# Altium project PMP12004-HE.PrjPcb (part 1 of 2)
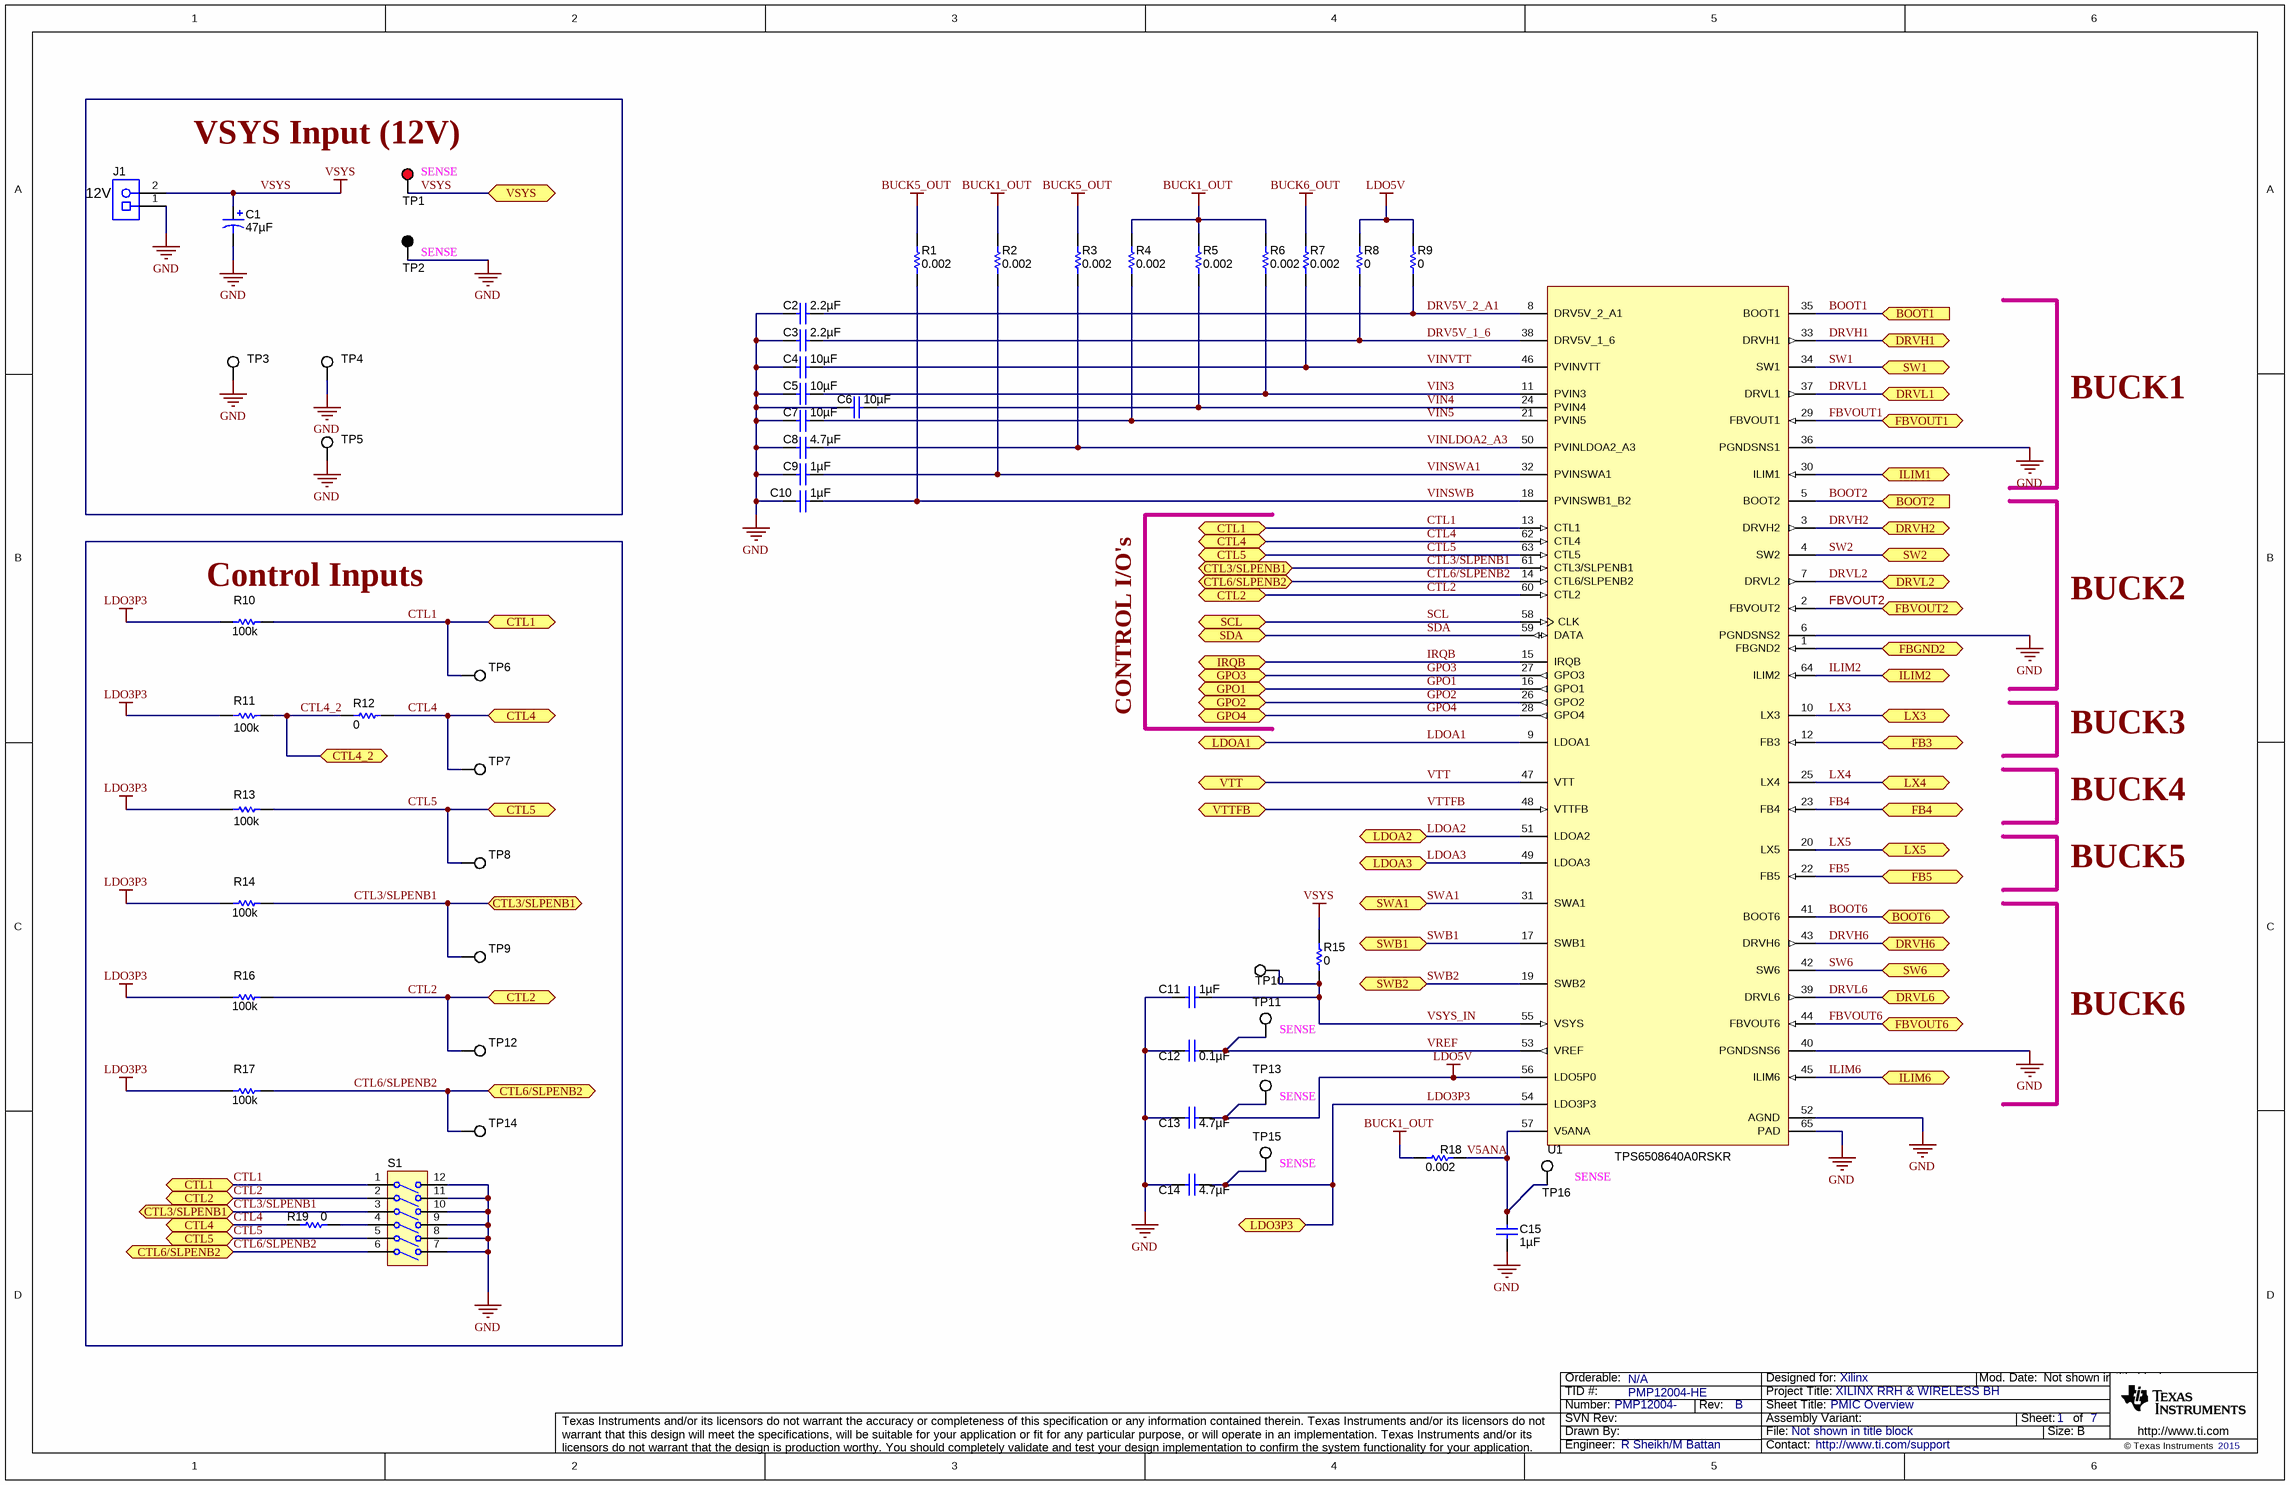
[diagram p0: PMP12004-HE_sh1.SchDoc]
TID: PMP12004-HE; TechSupport: http://www.ti.com/support; SCH_Rev: B; PRJ_Title: XILINX RRH & WIRELESS BH; PRJ_Number: PMP12004-; PRJ_Engineer: R Sheikh/M Battan; PRJ_Customer: Xilinx; PCB_Rev: RevA; PCB_Layout: Tessolve; EVM_Orderable: N/A; CopyrightYear: 2015
7 sheets, 361 parts. Net scope: flat (ports and power ports of the same name join across sheets).
Board file: PMP12004RevA.PcbDoc
Sheets:
  PMP12004-HE_sh1.SchDoc
  PMP12004-HE_sh2.SchDoc
  PMP12004-HE_sh3.SchDoc
  PMP12004-HE_sh4.SchDoc
  PMP12004-HE_sh5.SchDoc
  PMP12004-HE_sh6.SchDoc
  PMP12004-HE_Hardware.SchDoc

## Sheet PMP12004-HE_sh1.SchDoc: PMIC Overview
size 431 x 279 mm; Date: Not shown in title block; ApprovedBy: Not shown in title block; CheckedBy: Not shown in title block; Author: Not shown in title block; CompanyName: Not shown in title block; Engineer: Not shown in title block; Organization: Not shown in title block; Address1: Not shown in title block; Address2: Not shown in title block; Address3: Not shown in title block; Address4: Not shown in title block; DocumentNumber: 1; Revision: Use project parameter SCH_Rev; SheetNumber: 1; SheetTotal: 7; PageSetup: Record=PageOptions¦CenterHorizontal=True¦CenterVertical=True¦PrintScale=1.00¦XCorrection=1.00¦YCorrection=1.00¦PrintKind=0¦BorderSize=5000000¦LeftOffset=0¦BottomOffset=0¦Orientation=2¦PaperLength=1000¦PaperWidth=1000¦Scale=100¦PaperSource=15¦PrintQuality=600¦MediaType=1¦DitherType=10¦PaperKind=Letter¦PrintScaleMode=1

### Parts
C1  ValueDisplayed: 47µF  [7343-43]  (hidden comment: T495X476K035ATE300)
C2  ValueDisplayed: 2.2µF  [0402]  (hidden comment: CL05A225KQ5NNNC)
C3  ValueDisplayed: 2.2µF  [0402]  (hidden comment: CL05A225KQ5NNNC)
C4  ValueDisplayed: 10µF  [0402]  (hidden comment: CL05A106MP5NUNC)
C5  ValueDisplayed: 10µF  [0402]  (hidden comment: CL05A106MP5NUNC)
C6  ValueDisplayed: 10µF  [0402]  (hidden comment: CL05A106MP5NUNC)
C7  ValueDisplayed: 10µF  [0402]  (hidden comment: CL05A106MP5NUNC)
C8  ValueDisplayed: 4.7µF  [0402]  (hidden comment: GRM155R60J475ME47D)
C9  ValueDisplayed: 1µF  [0402]  (hidden comment: GRM155R61A105KE15D)
C10  ValueDisplayed: 1µF  [0402]  (hidden comment: GRM155R61A105KE15D)
C11  ValueDisplayed: 1µF  [0402]  (hidden comment: GRM155R6YA105KE11D)
C12  ValueDisplayed: 0.1µF  [0402]  (hidden comment: GRM155R61A104KA01D)
C13  ValueDisplayed: 4.7µF  [0603]  (hidden comment: GRM188R61A475ME15)
C14  ValueDisplayed: 4.7µF  [0603]  (hidden comment: GRM188R61A475ME15)
C15  ValueDisplayed: 1µF  [0402]  (hidden comment: GRM155R61A105KE15D)
J1  1935776  [Phoenix_1935776]  (value not drawn)
R1  ValueDisplayed: 0.002  [0508]  (hidden comment: KRL2012E-M-R002-G-T5)
R2  ValueDisplayed: 0.002  [0508]  (hidden comment: KRL2012E-M-R002-G-T5)
R3  ValueDisplayed: 0.002  [0508]  (hidden comment: KRL2012E-M-R002-G-T5)
R4  ValueDisplayed: 0.002  [0508]  (hidden comment: KRL2012E-M-R002-G-T5)
R5  ValueDisplayed: 0.002  [0508]  (hidden comment: KRL2012E-M-R002-G-T5)
R6  ValueDisplayed: 0.002  [0508]  (hidden comment: KRL2012E-M-R002-G-T5)
R7  ValueDisplayed: 0.002  [0508]  (hidden comment: KRL2012E-M-R002-G-T5)
R8  ValueDisplayed: 0  [0402]  (hidden comment: CRCW04020000Z0ED)
R9  ValueDisplayed: 0  [0402]  (hidden comment: CRCW04020000Z0ED)
R10  ValueDisplayed: 100k  [0402]  (hidden comment: CRCW0402100KJNED)
R11  value 100k  [0402]  (hidden comment: CRCW0402100KJNED)
R12  ValueDisplayed: 0  [0402]  (hidden comment: CRCW04020000Z0ED)
R13  Value_Code: 100k  [0402]  (hidden comment: CRCW0402100KJNED)
R14  ValueDisplayed: 100k  [0402]  (hidden comment: CRCW0402100KJNED)
R15  ValueDisplayed: 0  [0402]  (hidden comment: CRCW04020000Z0ED)
R16  ValueDisplayed: 100k  [0402]  (hidden comment: CRCW0402100KJNED)
R17  ValueDisplayed: 100k  [0402]  (hidden comment: CRCW0402100KJNED)
R18  ValueDisplayed: 0.002  [0508]  (hidden comment: KRL2012E-M-R002-G-T5)
R19  value 0  [0402]  (hidden comment: CRCW04020000Z0ED)
S1  SDA06H1SBD  [SW_SDA06H1SBD]  (value not drawn)
TP1  5000  [Keystone5000]  (value not drawn)
TP2  5001  [Keystone5001]  (value not drawn)
TP3  5015  [Testpoint_Keystone_Miniature]  (value not drawn)
TP4  5015  [Testpoint_Keystone_Miniature]  (value not drawn)
TP5  5015  [Testpoint_Keystone_Miniature]  (value not drawn)
TP6  5015  [Testpoint_Keystone_Miniature]  (value not drawn)
TP7  5015  [Testpoint_Keystone_Miniature]  (value not drawn)
TP8  5015  [Testpoint_Keystone_Miniature]  (value not drawn)
TP9  5015  [Testpoint_Keystone_Miniature]  (value not drawn)
TP10  5015  [Testpoint_Keystone_Miniature]  (value not drawn)
TP11  5015  [Testpoint_Keystone_Miniature]  (value not drawn)
TP12  5015  [Testpoint_Keystone_Miniature]  (value not drawn)
TP13  5015  [Testpoint_Keystone_Miniature]  (value not drawn)
TP14  5015  [Testpoint_Keystone_Miniature]  (value not drawn)
TP15  5015  [Testpoint_Keystone_Miniature]  (value not drawn)
TP16  5015  [Testpoint_Keystone_Miniature]  (value not drawn)
U1  TPS6508640A0RSKR  [RSK0064C]

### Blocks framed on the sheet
VSYS Input (12V): C1 J1 TP1-TP5
Control Inputs: R10-R14 R16 R17 R19 S1 TP6-TP9 TP12 TP14

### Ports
BOOT1 (in), BOOT2 (in), BOOT6 (bidir), CTL1 (bidir), CTL2 (bidir), CTL3/SLPENB1 (bidir), CTL4 (bidir), CTL4_2 (bidir), CTL5 (bidir), CTL6/SLPENB2 (bidir), DRVH1 (bidir), DRVH2 (bidir), DRVH6 (bidir), DRVL1 (bidir), DRVL2 (bidir), DRVL6 (bidir), FB3 (bidir), FB4 (bidir), FB5 (bidir), FBGND2 (bidir), FBVOUT1 (bidir), FBVOUT2 (bidir), FBVOUT6 (bidir), GPO1 (bidir), GPO2 (bidir), GPO3 (bidir), GPO4 (bidir), ILIM1 (bidir), ILIM2 (bidir), ILIM6 (bidir), IRQB (bidir), LDO3P3 (bidir), LDOA1 (bidir), LDOA2 (bidir), LDOA3 (bidir), LX3 (bidir), LX4 (bidir), LX5 (bidir), SCL (bidir), SDA (bidir), SW1 (bidir), SW2 (bidir), SW6 (bidir), SWA1 (bidir), SWB1 (bidir), SWB2 (bidir), VSYS (bidir), VTT (bidir), VTTFB (bidir)

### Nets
BUCK1_OUT: R2.1 R4.1 R5.1 R6.1 R18.2
BUCK5_OUT: R1.1 R3.1
BUCK6_OUT: R7.1
GND: C1.2(-) C2.2 C3.2 C4.2 C5.2 C6.2 C7.2 C8.2 C9.2 C10.2 C11.2 C12.2 C13.2 C14.2 C15.2 J1.1 S1.7(6A) S1.8(5A) S1.9(4A) S1.10(3A) S1.11(2A) S1.12(1A) TP2.1 TP3.1 TP4.1 TP5.1 U1.6(PGNDSNS2) U1.36(PGNDSNS1) U1.40(PGNDSNS6) U1.52(AGND) U1.65(PAD)
LDO3P3: C14.1 R10.2 R11.2 R13.2 R14.2 R16.2 R17.2 TP15.1 U1.54(LDO3P3) ; port LDO3P3
LDO5V: C13.1 R8.1 R9.1 TP13.1 U1.56(LDO5P0)
VSYS: C1.1(+) J1.2 R15.2 TP1.1 ; port VSYS
BOOT1: U1.35(BOOT1) ; port BOOT1
BOOT2: U1.5(BOOT2) ; port BOOT2
BOOT6: U1.41(BOOT6) ; port BOOT6
CTL1: R10.1 S1.1 TP6.1 U1.13(CTL1) ; port CTL1
CTL2: R16.1 S1.2 TP12.1 U1.60(CTL2) ; port CTL2
CTL3/SLPENB1: R14.1 S1.3 TP9.1 U1.61(CTL3/SLPENB1) ; port CTL3/SLPENB1
CTL4: R12.2 R19.1 TP7.1 U1.62(CTL4) ; port CTL4
CTL4_2: R11.1 R12.1 ; port CTL4_2
CTL5: R13.1 S1.5 TP8.1 U1.63(CTL5) ; port CTL5
CTL6/SLPENB2: R17.1 S1.6 TP14.1 U1.14(CTL6/SLPENB2) ; port CTL6/SLPENB2
DRV5V_1_6: C3.1 R8.2 U1.38(DRV5V_1_6)
DRV5V_2_A1: C2.1 R9.2 U1.8(DRV5V_2_A1)
DRVH1: U1.33(DRVH1) ; port DRVH1
DRVH2: U1.3(DRVH2) ; port DRVH2
DRVH6: U1.43(DRVH6) ; port DRVH6
DRVL1: U1.37(DRVL1) ; port DRVL1
DRVL2: U1.7(DRVL2) ; port DRVL2
DRVL6: U1.39(DRVL6) ; port DRVL6
FB3: U1.12(FB3) ; port FB3
FB4: U1.23(FB4) ; port FB4
FB5: U1.22(FB5) ; port FB5
FBGND2: U1.1(FBGND2) ; port FBGND2
FBVOUT1: U1.29(FBVOUT1) ; port FBVOUT1
FBVOUT2: U1.2(FBVOUT2) ; port FBVOUT2
FBVOUT6: U1.44(FBVOUT6) ; port FBVOUT6
GPO1: U1.16(GPO1) ; port GPO1
GPO2: U1.26(GPO2) ; port GPO2
GPO3: U1.27(GPO3) ; port GPO3
GPO4: U1.28(GPO4) ; port GPO4
ILIM1: U1.30(ILIM1) ; port ILIM1
ILIM2: U1.64(ILIM2) ; port ILIM2
ILIM6: U1.45(ILIM6) ; port ILIM6
IRQB: U1.15(IRQB) ; port IRQB
LDOA1: U1.9(LDOA1) ; port LDOA1
LDOA2: U1.51(LDOA2) ; port LDOA2
LDOA3: U1.49(LDOA3) ; port LDOA3
LX3: U1.10(LX3) ; port LX3
LX4: U1.25(LX4) ; port LX4
LX5: U1.20(LX5) ; port LX5
SCL: U1.58(CLK) ; port SCL
SDA: U1.59(DATA) ; port SDA
SW1: U1.34(SW1) ; port SW1
SW2: U1.4(SW2) ; port SW2
SW6: U1.42(SW6) ; port SW6
SWA1: U1.31(SWA1) ; port SWA1
SWB1: U1.17(SWB1) ; port SWB1
SWB2: U1.19(SWB2) ; port SWB2
V5ANA: C15.1 R18.1 TP16.1 U1.57(V5ANA)
VIN3: C5.1 R6.2 U1.11(PVIN3)
VIN4: C6.1 R5.2 U1.24(PVIN4)
VIN5: C7.1 R4.2 U1.21(PVIN5)
VINLDOA2_A3: C8.1 R3.2 U1.50(PVINLDOA2_A3)
VINSWA1: C9.1 R2.2 U1.32(PVINSWA1)
VINSWB: C10.1 R1.2 U1.18(PVINSWB1_B2)
VINVTT: C4.1 R7.2 U1.46(PVINVTT)
VREF: C12.1 TP11.1 U1.53(VREF)
VSYS_IN: C11.1 R15.1 TP10.1 U1.55(VSYS)
VTT: U1.47(VTT) ; port VTT
VTTFB: U1.48(VTTFB) ; port VTTFB
NetR19_2: R19.2 S1.4

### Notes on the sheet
- (near J1) 12V
- (near TP1) SENSE
- (near TP2) SENSE
- BUCK1
- BUCK2
- CONTROL I/O's
- BUCK3
- BUCK4
- BUCK5
- (near TP11) SENSE
- BUCK6
- (near TP13) SENSE
- (near TP15) SENSE
- SENSE

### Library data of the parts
C1 = T495X476K035ATE300: CAP, TA, 47 µF, 35 V, +/- 10%, 0.3 ohm, SMD; Manufacturer: Kemet; Polarized: Y; CompType: Capacitor; Value: 47uF; U/M: EA; Cap_F: 0.000047; Tolerance_%: 10; Value1: 0.3 ohm; VDC_V: 35; Value2: 35V; ESR_ohm: 0.3; IRMS_A: 0.667; TaMin_C: -55; TaMax_C: 125; Cap_Case: X
C2 C3 = CL05A225KQ5NNNC: CAP, CERM, 2.2 µF, 6.3 V, +/- 10%, X5R, 0402; Manufacturer: Samsung; Polarized: N; CompType: Capacitor; Value: 2.2uF; U/M: EA; Cap_F: 0.0000022; Tolerance_%: 10; Value1: Unknown; VDC_V: 6.3; Value2: 6.3V; TaMin_C: -55; TaMax_C: 85
C4-C7 = CL05A106MP5NUNC: CAP, CERM, 10 µF, 10 V, +/- 20%, X5R, 0402; Manufacturer: Samsung Electro-Mechanics; Polarized: N; CompType: Capacitor; Value: 10uF; U/M: EA; Cap_F: 0.00001; Tolerance_%: 20; Value1: Unknown; VDC_V: 10; Value2: 10V; TaMin_C: -55; TaMax_C: 85
C8 = GRM155R60J475ME47D: CAP, CERM, 4.7 µF, 6.3 V, +/- 20%, X5R, 0402; Manufacturer: MuRata; Polarized: N; CompType: Capacitor; Value: 4.7uF; U/M: EA; Cap_F: 0.0000047; Tolerance_%: 20; Value1: Unknown; VDC_V: 6.3; Value2: 6.3V; TaMin_C: -55; TaMax_C: 85
C9 C10 C15 = GRM155R61A105KE15D: CAP, CERM, 1 µF, 10 V, +/- 10%, X5R, 0402; Manufacturer: MuRata; Polarized: N; CompType: Capacitor; Value: 1uF; U/M: EA; Cap_F: 0.000001; Tolerance_%: 10; Value1: Unknown; Value2: 10V; TaMin_C: -55; TaMax_C: 85
C11 = GRM155R6YA105KE11D: CAP, CERM, 1 µF, 35 V, +/- 10%, X5R, 0402; Manufacturer: MuRata; Polarized: N; CompType: Capacitor; Value: 1uF; U/M: EA; Cap_F: 0.000001; Tolerance_%: 10; Value1: Unknown; VDC_V: 35; Value2: 35V; TaMin_C: -55; TaMax_C: 85
C12 = GRM155R61A104KA01D: CAP, CERM, 0.1 µF, 10 V, +/- 10%, X5R, 0402; Manufacturer: MuRata; Polarized: N; CompType: Capacitor; Value: 0.1uF; U/M: EA; Cap_F: 0.0000001; Tolerance_%: 10; Value1: Unknown; Value2: 10V; TaMin_C: -55; TaMax_C: 85
C13 C14 = GRM188R61A475ME15: CAP, CERM, 4.7 µF, 10 V, +/- 20%, X5R, 0603; Manufacturer: MuRata; Polarized: N; CompType: Capacitor; Value: 4.7uF; U/M: EA; Cap_F: 0.0000047; Tolerance_%: 20; Value1: Unknown; VDC_V: 10; Value2: 10V; TaMin_C: -55; TaMax_C: 85; AEC Category: Q200
J1 = 1935776: Terminal Block, 2x1, 5mm, Green, TH; Manufacturer: Phoenix Contact; SymbolCreator: a0412235; U/M: EA
R1-R7 R18 = KRL2012E-M-R002-G-T5: RES, 0.002, 2%, 1 W, 0508; Manufacturer: Susumu Co Ltd; CompType: Resistor; Value: 0.002; Value_Code: 2L000; Tolerance_%: 2; Power_W: 1; Value2: 1W; TempCo: 100 ppm/C; U/M: EA
R8 R9 R12 R15 = CRCW04020000Z0ED: RES, 0, 5%, 0.063 W, 0402; Manufacturer: Vishay-Dale; CompType: Resistor; Value: 0; Value_Code: 0000; Tolerance_%: 5; Power_W: 0.063; Value2: 0.063W; VDC_V: 50; TempCo: 200 ppm/C; EIA_Code: E24; U/M: EA
R10 R13 R14 R16 R17 = CRCW0402100KJNED: RES, 100 k, 5%, 0.063 W, 0402; Manufacturer: Vishay-Dale; CompType: Resistor; Value: 100k; Res_ohm: 100000; Tolerance_%: 5; Power_W: 0.063; Value2: 0.063W; VDC_V: 50; TempCo: 200 ppm/C; EIA_Code: E24; U/M: EA
R11 = CRCW0402100KJNED: RES, 100 k, 5%, 0.063 W, 0402; Manufacturer: Vishay-Dale; CompType: Resistor; ValueDisplayed: DNP; Res_ohm: 100000; Tolerance_%: 5; Power_W: 0.063; Value2: 0.063W; VDC_V: 50; TempCo: 200 ppm/C; EIA_Code: E24; U/M: EA
R19 = CRCW04020000Z0ED: RES, 0, 5%, 0.063 W, 0402; Manufacturer: Vishay-Dale; CompType: Resistor; ValueDisplayed: DNP; Value_Code: 0000; Tolerance_%: 5; Power_W: 0.063; Value2: 0.063W; TempCo: 200 ppm/C; EIA_Code: E24; U/M: EA
S1 = SDA06H1SBD: Switch, SPST 6Pos, SMT; Manufacturer: C&K Components; SymbolCreator: a0799628; VDC_V: 24; SwitchFunction: Off-On; PositionCount: 6; CurrentRating_mA: 25
TP1 = 5000: Test Point, Miniature, Red, TH; Manufacturer: Keystone; CompType: Test Point Loop; U/M: EA
TP2 = 5001: Test Point, Miniature, Black, TH; Manufacturer: Keystone; CompType: Test Point Loop; U/M: EA
TP3-TP16 = 5015: Test Point, Miniature, SMT; Manufacturer: Keystone; CompType: Test Point Loop; U/M: EA
U1 = TPS650860A0RSKR: Wide VIN, Flexible, Simple, Small, and Low-Cost PMU; Alternate PartNumber: TPS6508640A0RSKT; Manufacturer: Texas Instruments; SymbolCreator: Altium; CompType: IC; U/M: EA

## Sheet PMP12004-HE_sh2.SchDoc: 3.3V & VCCPINT Rails
size 431 x 279 mm; Date: Not shown in title block; ApprovedBy: Not shown in title block; CheckedBy: Not shown in title block; Author: Not shown in title block; CompanyName: Not shown in title block; Engineer: Not shown in title block; Organization: Not shown in title block; Address1: Not shown in title block; Address2: Not shown in title block; Address3: Not shown in title block; Address4: Not shown in title block; DocumentNumber: 2; Revision: Use project parameter SCH_Rev; SheetNumber: 2; SheetTotal: 7; PageSetup: Record=PageOptions¦CenterHorizontal=True¦CenterVertical=True¦PrintScale=1.00¦XCorrection=1.00¦YCorrection=1.00¦PrintKind=0¦BorderSize=5000000¦LeftOffset=0¦BottomOffset=0¦Orientation=2¦PaperLength=1000¦PaperWidth=1000¦Scale=100¦PaperSource=15¦PrintQuality=600¦MediaType=1¦DitherType=10¦PaperKind=Letter¦PrintScaleMode=1
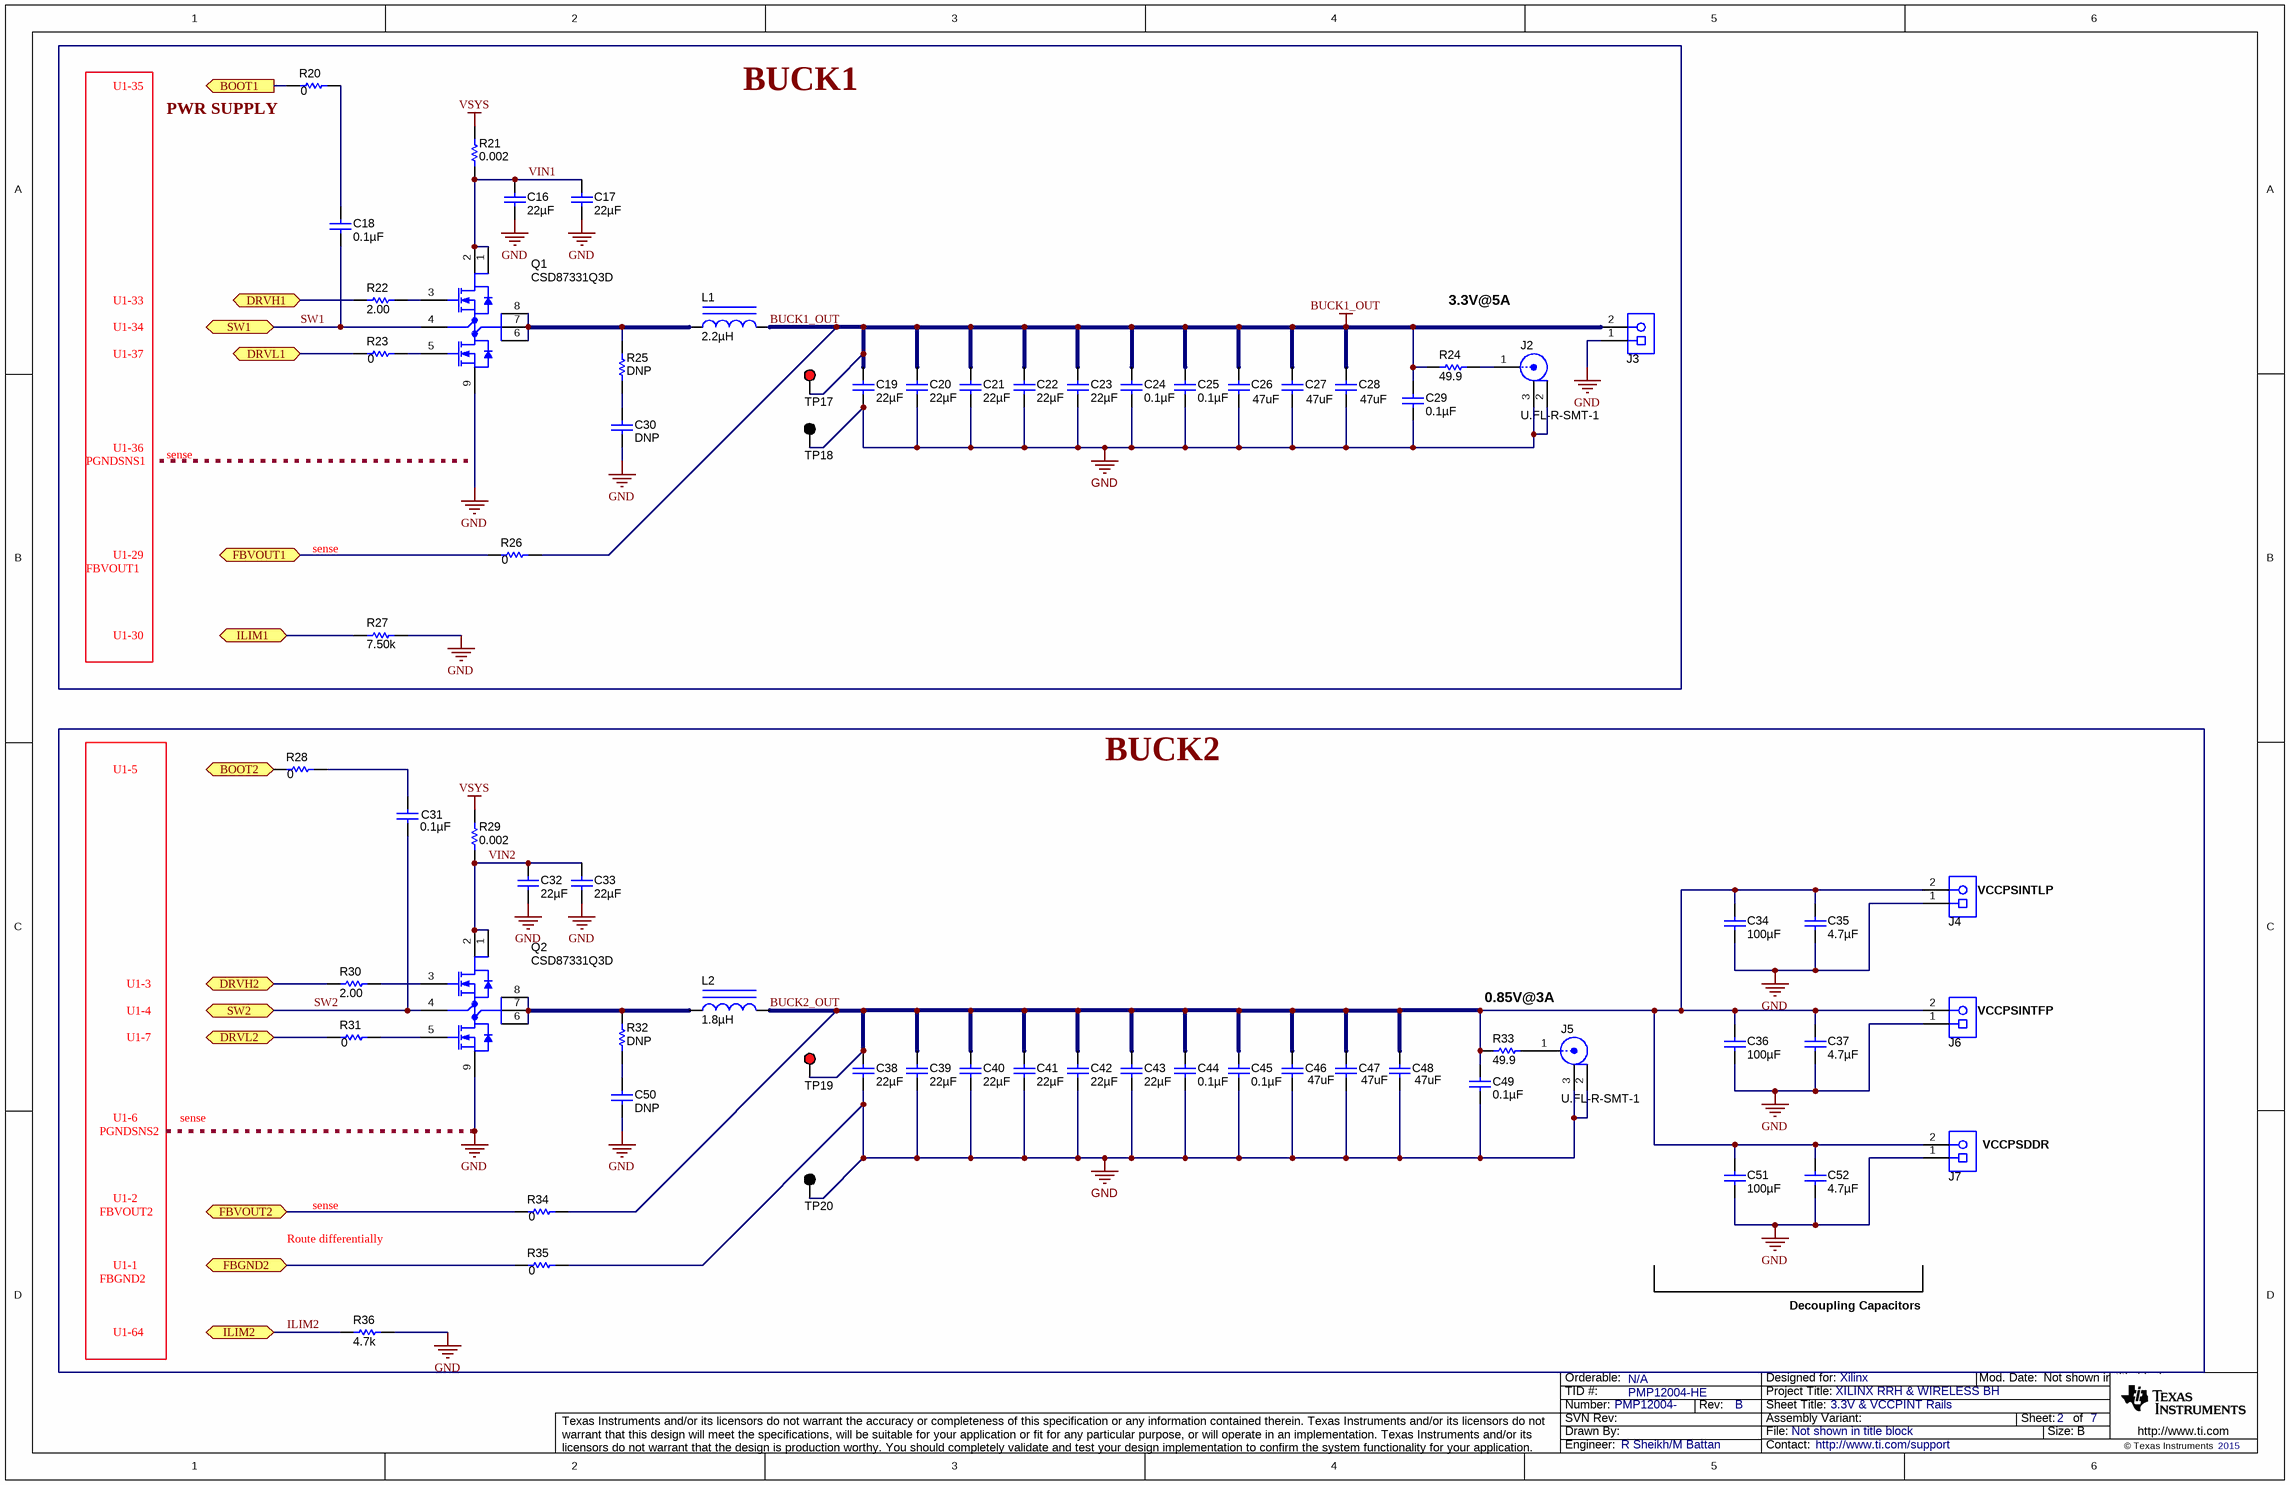
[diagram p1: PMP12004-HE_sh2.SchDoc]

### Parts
C16  ValueDisplayed: 22µF  [0805_HV]  (hidden comment: GRM21BR61E226ME44)
C17  ValueDisplayed: 22µF  [0805_HV]  (hidden comment: GRM21BR61E226ME44)
C18  ValueDisplayed: 0.1µF  [0402]  (hidden comment: GRM155R61A104KA01D)
C19  ValueDisplayed: 22µF  [0603]  (hidden comment: GRM188R60J226MEA0J)
C20  ValueDisplayed: 22µF  [0603]  (hidden comment: GRM188R60J226MEA0J)
C21  ValueDisplayed: 22µF  [0603]  (hidden comment: GRM188R60J226MEA0J)
C22  ValueDisplayed: 22µF  [0603]  (hidden comment: GRM188R60J226MEA0J)
C23  ValueDisplayed: 22µF  [0603]  (hidden comment: GRM188R60J226MEA0J)
C24  ValueDisplayed: 0.1µF  [0402]  (hidden comment: GRM155R61A104KA01D)
C25  ValueDisplayed: 0.1µF  [0402]  (hidden comment: GRM155R61A104KA01D)
C26  value 47uF  [0805_HV]  (hidden comment: GRM21BR61A476ME15)
C27  value 47uF  [0805_HV]  (hidden comment: GRM21BR61A476ME15)
C28  value 47uF  [0805_HV]  (hidden comment: GRM21BR61A476ME15)
C29  ValueDisplayed: 0.1µF  [0402]  (hidden comment: GRM155R61E104KA87D)
C30  ValueDisplayed: DNP  [0402]  (hidden comment: GRM155R71E682KA01D)
C31  ValueDisplayed: 0.1µF  [0402]  (hidden comment: GRM155R61A104KA01D)
C32  ValueDisplayed: 22µF  [0805_HV]  (hidden comment: GRM21BR61E226ME44)
C33  ValueDisplayed: 22µF  [0805_HV]  (hidden comment: GRM21BR61E226ME44)
C34  ValueDisplayed: 100µF  [0805_HV]  (hidden comment: GRM21BR60G107ME15L)
C35  ValueDisplayed: 4.7µF  [0603]  (hidden comment: GRM188R60J475ME19D)
C36  ValueDisplayed: 100µF  [0805_HV]  (hidden comment: GRM21BR60G107ME15L)
C37  ValueDisplayed: 4.7µF  [0603]  (hidden comment: GRM188R60J475ME19D)
C38  ValueDisplayed: 22µF  [0603]  (hidden comment: GRM188R60J226MEA0J)
C39  ValueDisplayed: 22µF  [0603]  (hidden comment: GRM188R60J226MEA0J)
C40  ValueDisplayed: 22µF  [0603]  (hidden comment: GRM188R60J226MEA0J)
C41  ValueDisplayed: 22µF  [0603]  (hidden comment: GRM188R60J226MEA0J)
C42  ValueDisplayed: 22µF  [0603]  (hidden comment: GRM188R60J226MEA0J)
C43  ValueDisplayed: 22µF  [0603]  (hidden comment: GRM188R60J226MEA0J)
C44  ValueDisplayed: 0.1µF  [0402]  (hidden comment: GRM155R61A104KA01D)
C45  ValueDisplayed: 0.1µF  [0402]  (hidden comment: GRM155R61A104KA01D)
C46  value 47uF  [0805_HV]  (hidden comment: GRM21BR61A476ME15)
C47  value 47uF  [0805_HV]  (hidden comment: GRM21BR61A476ME15)
C48  value 47uF  [0805_HV]  (hidden comment: GRM21BR61A476ME15)
C49  ValueDisplayed: 0.1µF  [0402]  (hidden comment: GRM155R61E104KA87D)
C50  ValueDisplayed: DNP  [0402]  (hidden comment: GRM155R71E682KA01D)
C51  ValueDisplayed: 100µF  [0805_HV]  (hidden comment: GRM21BR60G107ME15L)
C52  ValueDisplayed: 4.7µF  [0603]  (hidden comment: GRM188R60J475ME19D)
J2  U.FL-R-SMT-1  [CONN_UFL-R-SMT-1]
J3  1935776  [Phoenix_1935776]  (value not drawn)
J4  1935776  [Phoenix_1935776]  (value not drawn)
J5  U.FL-R-SMT-1  [CONN_UFL-R-SMT-1]
J6  1935776  [Phoenix_1935776]  (value not drawn)
J7  1935776  [Phoenix_1935776]  (value not drawn)
L1  ValueDisplayed: 2.2µH  [WE-LHMI_1040]  (hidden comment: 74437368022)
L2  ValueDisplayed: 1.8µH  [WE-HC6]  (hidden comment: 744325180)
Q1  CSD87331Q3D  [TRANS_NexFET_Q3D]
Q2  CSD87331Q3D  [TRANS_NexFET_Q3D]
R20  ValueDisplayed: 0  [0402]  (hidden comment: CRCW04020000Z0ED)
R21  ValueDisplayed: 0.002  [0508]  (hidden comment: KRL2012E-M-R002-G-T5)
R22  ValueDisplayed: 2.00  [0402]  (hidden comment: CRCW04022R00FKED)
R23  ValueDisplayed: 0  [0402]  (hidden comment: CRCW04020000Z0ED)
R24  ValueDisplayed: 49.9  [0402]  (hidden comment: CRCW040249R9FKED)
R25  ValueDisplayed: DNP  [0402]  (hidden comment: CRCW04022R20JNED)
R26  ValueDisplayed: 0  [0402]  (hidden comment: CRCW04020000Z0ED)
R27  ValueDisplayed: 7.50k  [0402]  (hidden comment: CRCW04027K50FKED)
R28  ValueDisplayed: 0  [0402]  (hidden comment: CRCW04020000Z0ED)
R29  ValueDisplayed: 0.002  [0508]  (hidden comment: KRL2012E-M-R002-G-T5)
R30  ValueDisplayed: 2.00  [0402]  (hidden comment: CRCW04022R00FKED)
R31  ValueDisplayed: 0  [0402]  (hidden comment: CRCW04020000Z0ED)
R32  ValueDisplayed: DNP  [0402]  (hidden comment: CRCW04022R20JNED)
R33  ValueDisplayed: 49.9  [0402]  (hidden comment: CRCW040249R9FKED)
R34  ValueDisplayed: 0  [0402]  (hidden comment: CRCW04020000Z0ED)
R35  ValueDisplayed: 0  [0402]  (hidden comment: CRCW04020000Z0ED)
R36  ValueDisplayed: 4.7k  [0402]  (hidden comment: CRCW04024K70JNED)
TP17  5000  [Keystone5000]  (value not drawn)
TP18  5001  [Keystone5001]  (value not drawn)
TP19  5000  [Keystone5000]  (value not drawn)
TP20  5001  [Keystone5001]  (value not drawn)

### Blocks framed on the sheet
BUCK1: C16-C30 J2 J3 L1 Q1 R20-R27 TP17 TP18
BUCK2: C31-C52 J4-J7 L2 Q2 R28-R36 TP19 TP20

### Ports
BOOT1 (out), BOOT2 (out), DRVH1 (bidir), DRVH2 (bidir), DRVL1 (bidir), DRVL2 (bidir), FBGND2 (bidir), FBVOUT1 (bidir), FBVOUT2 (bidir), ILIM1 (bidir), ILIM2 (bidir), SW1 (bidir), SW2 (bidir)

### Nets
BUCK1_OUT: C19.1 C20.1 C21.1 C22.1 C23.1 C24.1 C25.1 C26.1 C27.1 C28.1 C29.1 J3.2 L1.2 R24.1 R26.2 TP17.1
GND: C16.2 C17.2 C19.2 C20.2 C21.2 C22.2 C23.2 C24.2 C25.2 C26.2 C27.2 C28.2 C29.2 C30.2 C32.2 C33.2 C34.2 C35.2 C36.2 C37.2 C38.2 C39.2 C40.2 C41.2 C42.2 C43.2 C44.2 C45.2 C46.2 C47.2 C48.2 C49.2 C50.2 C51.2 C52.2 J2.2 J2.3 J3.1 J4.1 J5.2 J5.3 J6.1 J7.1 Q1.9(PGND) Q2.9(PGND) R27.2 R35.2 R36.2 TP18.1 TP20.1
VSYS: R21.1 R29.1
BOOT1: R20.1 ; port BOOT1
BOOT2: R28.1 ; port BOOT2
BUCK2_OUT: C34.1 C35.1 C36.1 C37.1 C38.1 C39.1 C40.1 C41.1 C42.1 C43.1 C44.1 C45.1 C46.1 C47.1 C48.1 C49.1 C51.1 C52.1 J4.2 J6.2 J7.2 L2.2 R33.1 R34.2 TP19.1
DRVH1: R22.1 ; port DRVH1
DRVH2: R30.1 ; port DRVH2
DRVL1: R23.1 ; port DRVL1
DRVL2: R31.1 ; port DRVL2
FBGND2: R35.1 ; port FBGND2
FBVOUT1: R26.1 ; port FBVOUT1
FBVOUT2: R34.1 ; port FBVOUT2
ILIM1: R27.1 ; port ILIM1
ILIM2: R36.1 ; port ILIM2
SW1: C18.1 Q1.4(TGR) ; port SW1
SW2: C31.1 Q2.4(TGR) ; port SW2
VIN1: C16.1 C17.1 Q1.1(VIN) Q1.2(VIN) R21.2
VIN2: C32.1 C33.1 Q2.1(VIN) Q2.2(VIN) R29.2
NetC18_2: C18.2 R20.2
NetC30_1: C30.1 R25.1
NetC31_2: C31.2 R28.2
NetC50_1: C50.1 R32.1
NetJ2_1: J2.1 R24.2
NetJ5_1: J5.1 R33.2
NetL1_1: L1.1 Q1.6(VSW) Q1.7(VSW) Q1.8(VSW) R25.2
NetL2_1: L2.1 Q2.6(VSW) Q2.7(VSW) Q2.8(VSW) R32.2
NetQ1_3: Q1.3(TG) R22.2
NetQ1_5: Q1.5(BG) R23.2
NetQ2_3: Q2.3(TG) R30.2
NetQ2_5: Q2.5(BG) R31.2

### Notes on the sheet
- U1-35
- (near R20) PWR SUPPLY
- U1-33
- 3.3V@5A
- U1-34
- U1-37
- PGNDSNS1
- U1-36
- sense
- FBVOUT1
- U1-29
- U1-30
- U1-5
- (near J4) VCCPSINTLP
- U1-3
- U1-4
- U1-7
- 0.85V@3A
- (near J6) VCCPSINTFP
- PGNDSNS2
- U1-6
- (near J7) VCCPSDDR
- FBVOUT2
- U1-2
- Route differentially
- FBGND2
- U1-1
- Decoupling Capacitors
- U1-64

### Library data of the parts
C16 C17 C32 C33 = GRM21BR61E226ME44: CAP, CERM, 22 µF, 25 V, +/- 20%, X5R, 0805; Manufacturer: MuRata; Polarized: N; CompType: Capacitor; Value: 22uF; U/M: EA; Cap_F: 0.000022; Tolerance_%: 20; Value1: Unknown; VDC_V: 25; Value2: 25V; TaMin_C: -55; TaMax_C: 85; Cap_Case: 0805
C18 C24 C25 C31 C44 C45 = GRM155R61A104KA01D: as C12 on sheet PMP12004-HE_sh1
C19-C23 C38-C43 = GRM188R60J226MEA0J: CAP, CERM, 22 µF, 6.3 V, +/- 20%, X5R, 0603; Manufacturer: MuRata; Polarized: N; CompType: Capacitor; Value: 22uF; U/M: EA; Cap_F: 0.000022; Tolerance_%: 20; Value1: Unknown; VDC_V: 6.3; Value2: 6.3V; TaMin_C: -55; TaMax_C: 85
C26-C28 C46-C48 = GRM21BR61A476ME15: CAP, CERM, 47 µF, 10 V, +/- 20%, X5R, 0805; Manufacturer: MuRata; Polarized: N; CompType: Capacitor; ValueDisplayed: DNP; U/M: EA; Cap_F: 0.000047; Tolerance_%: 20; Value1: Unknown; VDC_V: 10; Value2: 10V; TaMin_C: -55; TaMax_C: 85; Cap_Case: 0805; AEC Category: Q200
C29 C49 = GRM155R61E104KA87D: CAP, CERM, 0.1 µF, 25 V, +/- 10%, X5R, 0402; Manufacturer: MuRata; Polarized: N; CompType: Capacitor; Value: 0.1uF; U/M: EA; Cap_F: 0.0000001; Tolerance_%: 10; Value1: Unknown; VDC_V: 25; Value2: 25V; TaMin_C: -55; TaMax_C: 85
C30 C50 = GRM155R71E682KA01D: CAP, CERM, 6800 pF, 25 V, +/- 10%, X7R, 0402; Manufacturer: MuRata; Polarized: N; CompType: Capacitor; Value: DNP; U/M: EA; Cap_F: 0.0000000068; Tolerance_%: 10; Value1: Unknown; VDC_V: 25; Value2: 25V; TaMin_C: -55; TaMax_C: 125
C34 C36 C51 = GRM21BR60G107ME15L: CAP, CERM, 100 µF, 4 V, +/- 20%, X5R, 0805; Manufacturer: MuRata; Polarized: N; CompType: Capacitor; Value: 100uF; U/M: EA; Cap_F: 0.0001; Tolerance_%: 20; Value1: Unknown; VDC_V: 4; Value2: 4V; TaMin_C: -55; TaMax_C: 85; Cap_Case: 0805; AEC Category: Q200
C35 C37 C52 = GRM188R60J475ME19D: CAP, CERM, 4.7 µF, 6.3 V, +/- 20%, X5R, 0603; Manufacturer: MuRata; Polarized: N; CompType: Capacitor; Value: 4.7uF; U/M: EA; Cap_F: 0.0000047; Tolerance_%: 20; ESR_ohm: 0.001; Value1: 0.001 ohm; VDC_V: 6.3; Value2: 6.3V; TaMin_C: -55; TaMax_C: 125; AEC Category: Q200
J2 J5 = U.FL-R-SMT-1: Connector, Ultra-Mini Coaxial, SMD; Manufacturer: Hirose Electric Co. Ltd.; SymbolCreator: a0412235; U/M: EA
J3 J4 J6 J7 = 1935776: as J1 on sheet PMP12004-HE_sh1
L1 = 74437368022: Inductor, Shielded Drum Core, Powdered Iron, 2.2 µH, 10 A, 0.0065 ohm, SMD; Manufacturer: Wurth Elektronik; Value: 2.2uH; Ind_H: 2.2E-6; Imax_A: 10; Irms: 10A @ 40C rise; Isat: 28A @ 20% inductance drop; DCR_ohm: 0.0065; Value2: 10A; AEC Category: Q200
L2 = 744325180: Inductor, Shielded Drum Core, Superflux, 1.8 µH, 16 A, 0.0035 ohm, SMD; Manufacturer: Wurth Elektronik; Value: 1.8uH; Ind_H: 1.8E-6; Imax_A: 16; Irms: 16A @ 50C rise; Isat: 18A @ 30% inductance drop; DCR_ohm: 0.0035; Value2: 16A; AEC Category: Q200
Q1 Q2 = CSD87331Q3D: MOSFET, N-CH, 30 V, 15 A, 3.4x1.4x3.4mm; Manufacturer: Texas Instruments; Alternate Manufacturer: None; SymbolCreator: a0799628; U/M: EA; ChType: N; Value: 30V; VdsMax_V: 30; Value1: 0.018 ohm; Rdson45_ohm: 0.018; Value2: 2.7 nC; QgTyp_nC: 2.7; Vgs_V: 8; IdsMax_A: 15; AEC Category: Q101
R20 R23 R26 R28 R31 R34 R35 = CRCW04020000Z0ED: as R8 on sheet PMP12004-HE_sh1
R21 R29 = KRL2012E-M-R002-G-T5: as R1 on sheet PMP12004-HE_sh1
R22 R30 = CRCW04022R00FKED: RES, 2.00, 1%, 0.063 W, 0402; Manufacturer: Vishay-Dale; CompType: Resistor; Value: 2.00; Res_ohm: 2; Value_Code: 2R00; Tolerance_%: 1; Power_W: 0.063; Value2: 0.063W; VDC_V: 50; TempCo: 100 ppm/C; EIA_Code: E96; U/M: EA; AEC Category: Q200
R24 R33 = CRCW040249R9FKED: RES, 49.9, 1%, 0.063 W, 0402; Manufacturer: Vishay-Dale; CompType: Resistor; Value: 49.9; Value_Code: 49R9; Tolerance_%: 1; Power_W: 0.063; Value2: 0.063W; VDC_V: 50; TempCo: 100 ppm/C; EIA_Code: E96; U/M: EA
R25 R32 = CRCW04022R20JNED: RES, 2.2, 5%, 0.063 W, 0402; Manufacturer: Vishay-Dale; CompType: Resistor; Value: DNP; Res_ohm: 2.2; Value_Code: 2R20; Tolerance_%: 5; Power_W: 0.063; Value2: 0.063W; VDC_V: 50; TempCo: 200 ppm/C; EIA_Code: E24; U/M: EA
R27 = CRCW04027K50FKED: RES, 7.50 k, 1%, 0.063 W, 0402; Manufacturer: Vishay-Dale; CompType: Resistor; Value: 7.50k; Res_ohm: 7500; Value_Code: 7k50; Tolerance_%: 1; Power_W: 0.063; Value2: 0.063W; VDC_V: 50; TempCo: 100 ppm/C; EIA_Code: E96; U/M: EA; AEC Category: Q200
R36 = CRCW04024K70JNED: RES, 4.7 k, 5%, 0.063 W, 0402; Manufacturer: Vishay-Dale; CompType: Resistor; Value: 4.7k; Res_ohm: 4700; Value_Code: 4k70; Tolerance_%: 5; Power_W: 0.063; Value2: 0.063W; VDC_V: 50; TempCo: 200 ppm/C; EIA_Code: E24; U/M: EA; AEC Category: Q200
TP17 TP19 = 5000: as TP1 on sheet PMP12004-HE_sh1
TP18 TP20 = 5001: as TP2 on sheet PMP12004-HE_sh1

## Sheet PMP12004-HE_sh3.SchDoc: VMGTA Rails
size 431 x 279 mm; Date: Not shown in title block; ApprovedBy: Not shown in title block; CheckedBy: Not shown in title block; Author: Not shown in title block; CompanyName: Not shown in title block; Engineer: Not shown in title block; Organization: Not shown in title block; Address1: Not shown in title block; Address2: Not shown in title block; Address3: Not shown in title block; Address4: Not shown in title block; DocumentNumber: 3; Revision: Use project parameter SCH_Rev; SheetNumber: 3; SheetTotal: 7; PageSetup: Record=PageOptions¦CenterHorizontal=True¦CenterVertical=True¦PrintScale=1.00¦XCorrection=1.00¦YCorrection=1.00¦PrintKind=0¦BorderSize=5000000¦LeftOffset=0¦BottomOffset=0¦Orientation=2¦PaperLength=1000¦PaperWidth=1000¦Scale=100¦PaperSource=15¦PrintQuality=600¦MediaType=1¦DitherType=10¦PaperKind=Letter¦PrintScaleMode=1
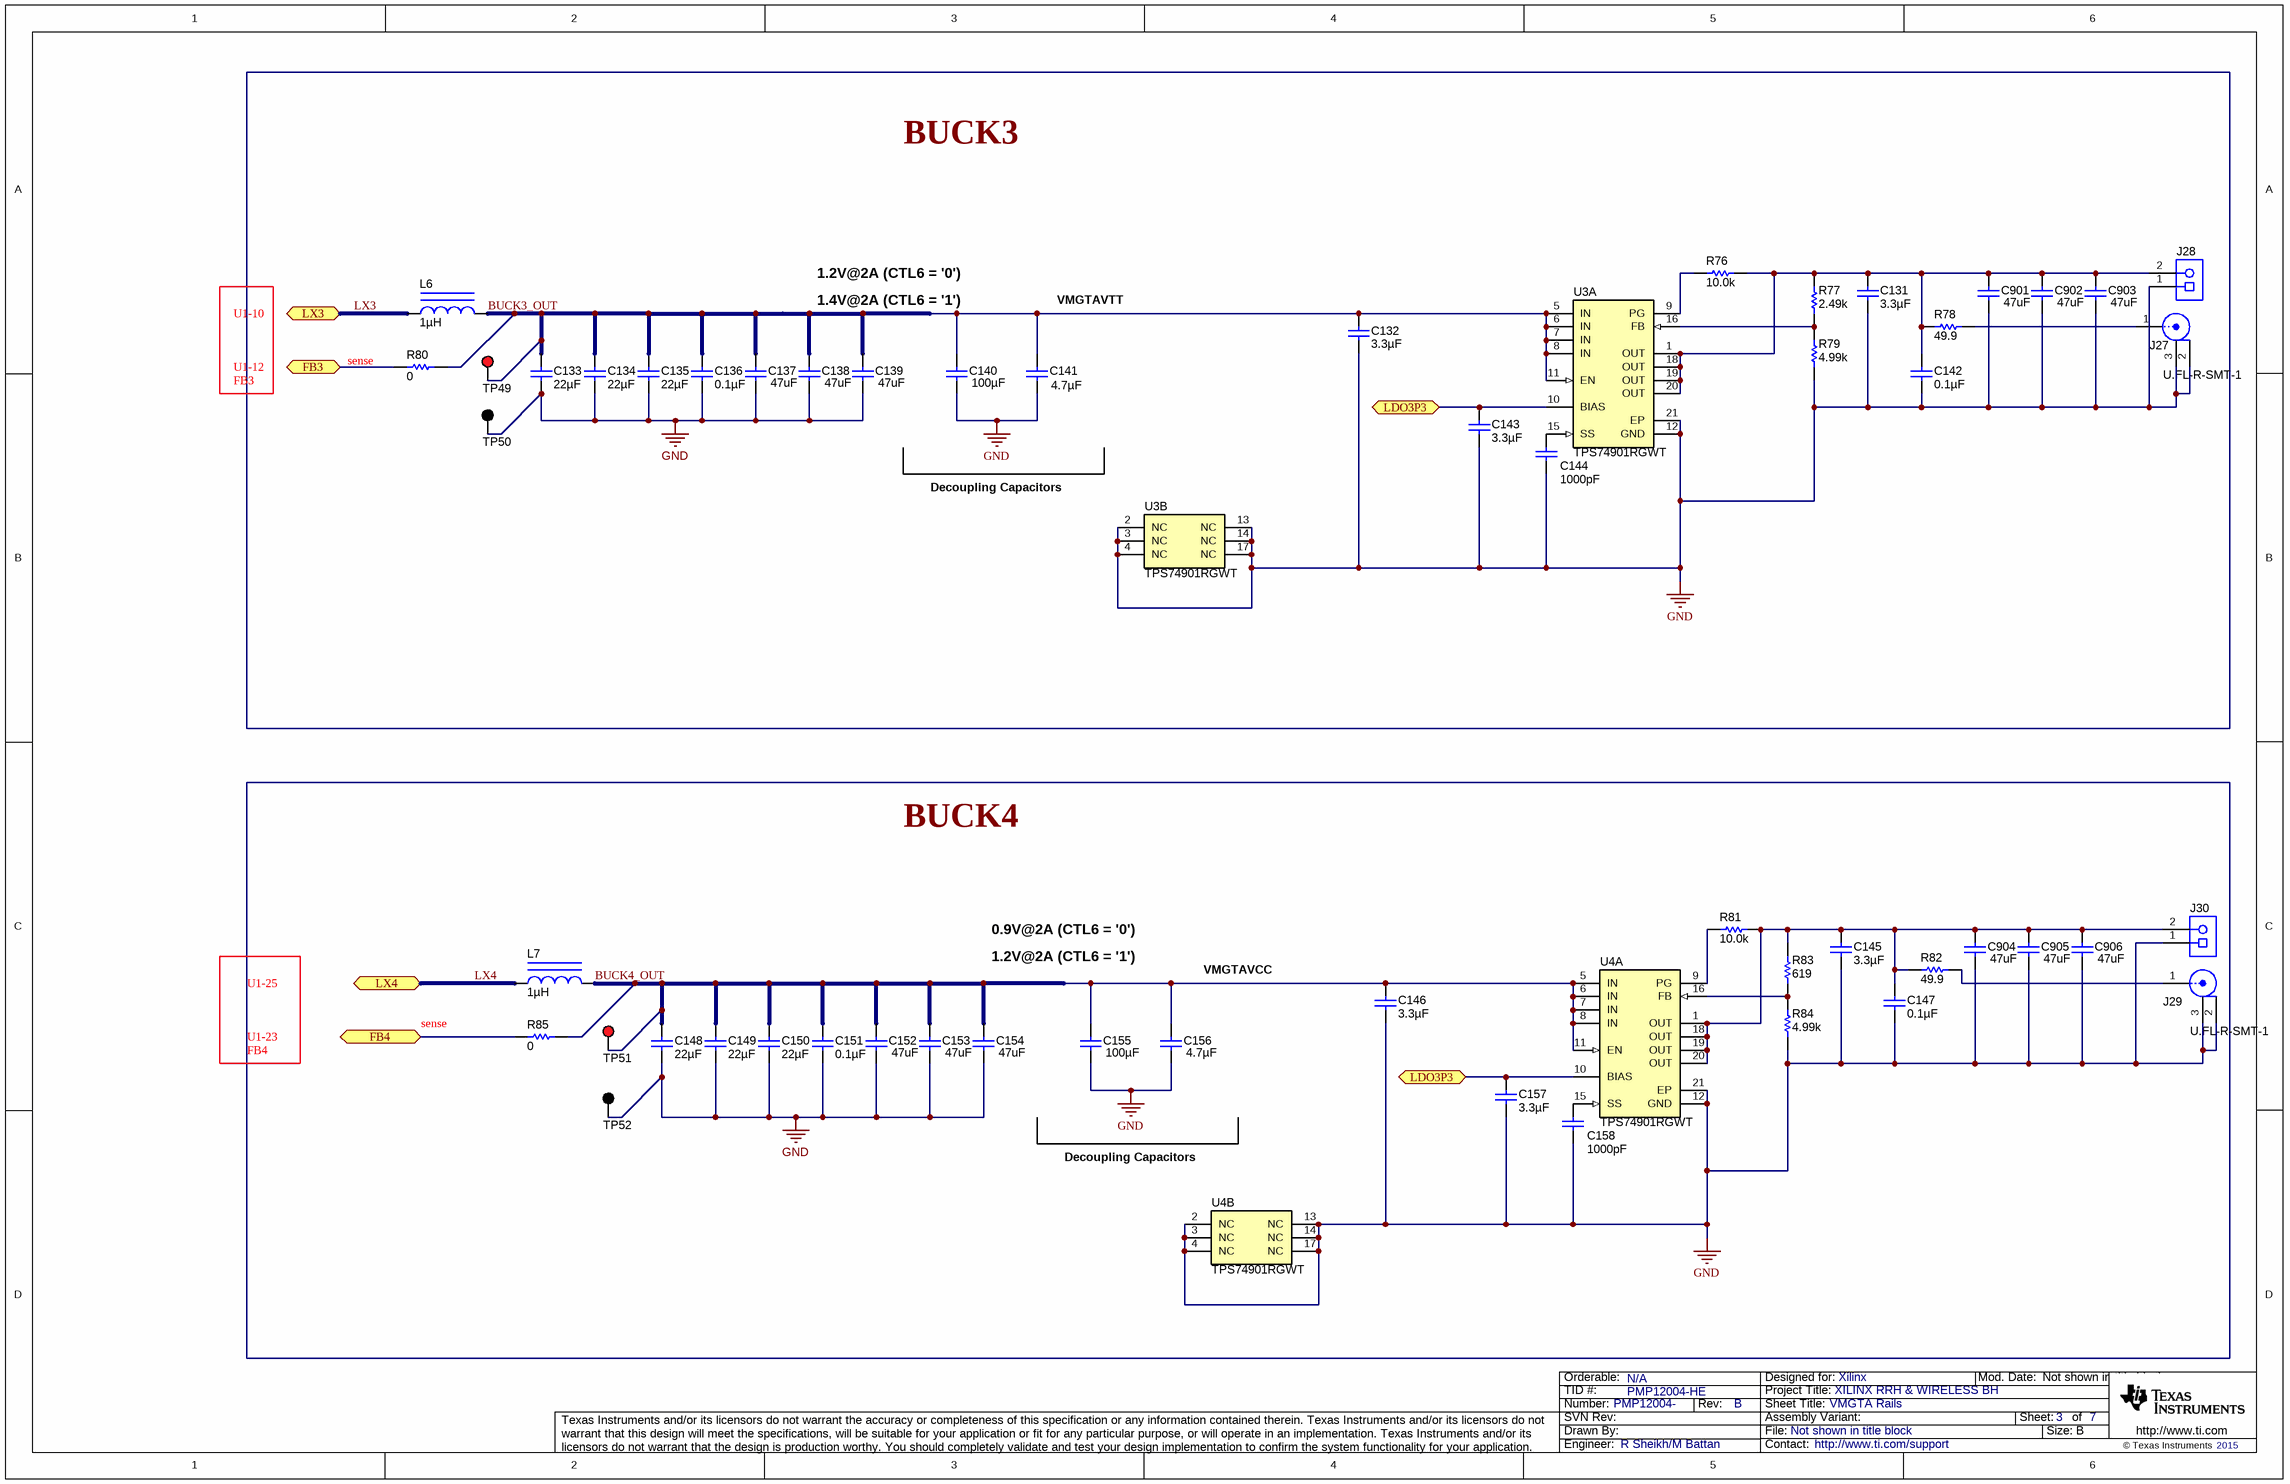
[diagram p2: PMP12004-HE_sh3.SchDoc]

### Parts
C131  ValueDisplayed: 3.3µF  [0603]  (hidden comment: GRM188R61A335KE15D)
C132  ValueDisplayed: 3.3µF  [0603]  (hidden comment: GRM188R61A335KE15D)
C133  ValueDisplayed: 22µF  [0603]  (hidden comment: GRM188R60J226MEA0J)
C134  ValueDisplayed: 22µF  [0603]  (hidden comment: GRM188R60J226MEA0J)
C135  ValueDisplayed: 22µF  [0603]  (hidden comment: GRM188R60J226MEA0J)
C136  ValueDisplayed: 0.1µF  [0402]  (hidden comment: GRM155R61A104KA01D)
C137  value 47uF  [0805_HV]  (hidden comment: GRM21BR61A476ME15)
C138  value 47uF  [0805_HV]  (hidden comment: GRM21BR61A476ME15)
C139  value 47uF  [0805_HV]  (hidden comment: GRM21BR61A476ME15)
C140  value 100µF  [0805_HV]  (hidden comment: GRM21BR60G107ME15L)
C141  value 4.7µF  [0603]  (hidden comment: GRM188R60J475ME19D)
C142  ValueDisplayed: 0.1µF  [0402]  (hidden comment: GRM155R61E104KA87D)
C143  ValueDisplayed: 3.3µF  [0603]  (hidden comment: GRM188R61A335KE15D)
C144  ValueDisplayed: 1000pF  [0402]  (hidden comment: GRM155R60J102KA01D)
C145  ValueDisplayed: 3.3µF  [0603]  (hidden comment: GRM188R61A335KE15D)
C146  ValueDisplayed: 3.3µF  [0603]  (hidden comment: GRM188R61A335KE15D)
C147  ValueDisplayed: 0.1µF  [0402]  (hidden comment: GRM155R61E104KA87D)
C148  ValueDisplayed: 22µF  [0603]  (hidden comment: C1608X5R0J226M080AC)
C149  ValueDisplayed: 22µF  [0603]  (hidden comment: C1608X5R0J226M080AC)
C150  ValueDisplayed: 22µF  [0603]  (hidden comment: C1608X5R0J226M080AC)
C151  ValueDisplayed: 0.1µF  [0402]  (hidden comment: GRM155R61A104KA01D)
C152  value 47uF  [0805_HV]  (hidden comment: GRM21BR61A476ME15)
C153  value 47uF  [0805_HV]  (hidden comment: GRM21BR61A476ME15)
C154  value 47uF  [0805_HV]  (hidden comment: GRM21BR61A476ME15)
C155  value 100µF  [0805_HV]  (hidden comment: GRM21BR60G107ME15L)
C156  value 4.7µF  [0603]  (hidden comment: GRM188R60J475ME19D)
C157  ValueDisplayed: 3.3µF  [0603]  (hidden comment: GRM188R61A335KE15D)
C158  ValueDisplayed: 1000pF  [0402]  (hidden comment: GRM155R60J102KA01D)
C901  value 47uF  [0805_HV]  (hidden comment: GRM21BR61A476ME15)
C902  value 47uF  [0805_HV]  (hidden comment: GRM21BR61A476ME15)
C903  value 47uF  [0805_HV]  (hidden comment: GRM21BR61A476ME15)
C904  value 47uF  [0805_HV]  (hidden comment: GRM21BR61A476ME15)
C905  value 47uF  [0805_HV]  (hidden comment: GRM21BR61A476ME15)
C906  value 47uF  [0805_HV]  (hidden comment: GRM21BR61A476ME15)
J27  U.FL-R-SMT-1  [CONN_UFL-R-SMT-1]
J28  1935776  [Phoenix_1935776]  (value not drawn)
J29  U.FL-R-SMT-1  [CONN_UFL-R-SMT-1]
J30  1935776  [Phoenix_1935776]  (value not drawn)
L6  ValueDisplayed: 1µH  [WE-PD-M]  (hidden comment: 744777001)
L7  ValueDisplayed: 1µH  [WE-PD-M]  (hidden comment: 744777001)
R76  ValueDisplayed: 10.0k  [0603]  (hidden comment: RT0603DRE0710KL)
R77  ValueDisplayed: 2.49k  [0603]  (hidden comment: RT0603DRE072K49L)
R78  ValueDisplayed: 49.9  [0402]  (hidden comment: CRCW040249R9FKED)
R79  ValueDisplayed: 4.99k  [0603]  (hidden comment: RT0603DRE074K99L)
R80  ValueDisplayed: 0  [0402]  (hidden comment: CRCW04020000Z0ED)
R81  ValueDisplayed: 10.0k  [0603]  (hidden comment: RT0603DRE0710KL)
R82  ValueDisplayed: 49.9  [0402]  (hidden comment: CRCW040249R9FKED)
R83  ValueDisplayed: 619  [0603]  (hidden comment: RT0603DRE07619RL)
R84  ValueDisplayed: 4.99k  [0603]  (hidden comment: RT0603DRE074K99L)
R85  ValueDisplayed: 0  [0402]  (hidden comment: CRCW04020000Z0ED)
TP49  5000  [Keystone5000]  (value not drawn)
TP50  5001  [Keystone5001]  (value not drawn)
TP51  5000  [Keystone5000]  (value not drawn)
TP52  5001  [Keystone5001]  (value not drawn)
U3  TPS74901RGWT  [RGW0020A]  (parts A,B of 2)
U4  TPS74901RGWT  [RGW0020A]  (parts A,B of 2)

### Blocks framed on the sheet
BUCK3: C131-C144 C901-C903 J27 J28 L6 R76-R80 TP49 TP50 U3
BUCK4: C145-C158 C904-C906 J29 J30 L7 R81-R85 TP51 TP52 U4

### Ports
FB3 (bidir), FB4 (bidir), LDO3P3 (bidir), LX3 (bidir), LX4 (bidir)

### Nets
GND: C131.2 C132.2 C133.2 C134.2 C135.2 C136.2 C137.2 C138.2 C139.2 C140.2 C141.2 C142.2 C143.2 C144.2 C145.2 C146.2 C147.2 C148.2 C149.2 C150.2 C151.2 C152.2 C153.2 C154.2 C155.2 C156.2 C157.2 C158.2 C901.2 C902.2 C903.2 C904.2 C905.2 C906.2 J27.2 J27.3 J28.1 J29.2 J29.3 J30.1 R79.1 R84.1 TP50.1 TP52.1 U3.2(NC) U3.3(NC) U3.4(NC) U3.12(GND) U3.13(NC) U3.14(NC) U3.17(NC) U3.21(EP) U4.2(NC) U4.3(NC) U4.4(NC) U4.12(GND) U4.13(NC) U4.14(NC) U4.17(NC) U4.21(EP)
LDO3P3: C143.1 C157.1 U3.10(BIAS) U4.10(BIAS) ; port LDO3P3
BUCK3_OUT: C132.1 C133.1 C134.1 C135.1 C136.1 C137.1 C138.1 C139.1 C140.1 C141.1 L6.2 R80.2 TP49.1 U3.5(IN) U3.6(IN) U3.7(IN) U3.8(IN) U3.11(EN)
BUCK4_OUT: C146.1 C148.1 C149.1 C150.1 C151.1 C152.1 C153.1 C154.1 C155.1 C156.1 L7.2 R85.2 TP51.1 U4.5(IN) U4.6(IN) U4.7(IN) U4.8(IN) U4.11(EN)
FB3: R80.1 ; port FB3
FB4: R85.1 ; port FB4
LX3: L6.1 ; port LX3
LX4: L7.1 ; port LX4
NetC131_1: C131.1 C142.1 C901.1 C902.1 C903.1 J28.2 R76.1 R77.2 R78.1 U3.1(OUT) U3.18(OUT) U3.19(OUT) U3.20(OUT)
NetC144_1: C144.1 U3.15(SS)
NetC145_1: C145.1 C147.1 C904.1 C905.1 C906.1 J30.2 R81.1 R82.1 R83.2 U4.1(OUT) U4.18(OUT) U4.19(OUT) U4.20(OUT)
NetC158_1: C158.1 U4.15(SS)
NetJ27_1: J27.1 R78.2
NetJ29_1: J29.1 R82.2
NetR76_2: R76.2 U3.9(PG)
NetR77_1: R77.1 R79.2 U3.16(FB)
NetR81_2: R81.2 U4.9(PG)
NetR83_1: R83.1 R84.2 U4.16(FB)

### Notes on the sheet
- 1.4V@2A (CTL6 = '1')
- 1.2V@2A (CTL6 = '0')
- VMGTAVTT
- U1-10
- U1-12
- (near R80) sense
- FB3
- Decoupling Capacitors
- 1.2V@2A (CTL6 = '1')
- 0.9V@2A (CTL6 = '0')
- VMGTAVCC
- U1-25
- U1-23
- sense
- FB4

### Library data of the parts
C131 C132 C143 C145 C146 C157 = GRM188R61A335KE15D: CAP, CERM, 3.3 µF, 10 V, +/- 10%, X5R, 0603; Manufacturer: MuRata; Polarized: N; CompType: Capacitor; Value: 3.3uF; U/M: EA; Cap_F: 0.0000033; Tolerance_%: 10; ESR_ohm: 0.005; Value1: 0.005 ohm; Value2: 10V; IRMS_A: 1.7; TaMin_C: -55; TaMax_C: 85; AEC Category: Q200
C133-C135 = GRM188R60J226MEA0J: as C19 on sheet PMP12004-HE_sh2
C136 C151 = GRM155R61A104KA01D: as C12 on sheet PMP12004-HE_sh1
C137-C139 C152-C154 C901-C906 = GRM21BR61A476ME15: as C26 on sheet PMP12004-HE_sh2
C140 C155 = GRM21BR60G107ME15L: CAP, CERM, 100 µF, 4 V, +/- 20%, X5R, 0805; Manufacturer: MuRata; Polarized: N; CompType: Capacitor; ValueDisplayed: DNP; U/M: EA; Cap_F: 0.0001; Tolerance_%: 20; Value1: Unknown; VDC_V: 4; Value2: 4V; TaMin_C: -55; TaMax_C: 85; Cap_Case: 0805; AEC Category: Q200
C141 C156 = GRM188R60J475ME19D: CAP, CERM, 4.7 µF, 6.3 V, +/- 20%, X5R, 0603; Manufacturer: MuRata; Polarized: N; CompType: Capacitor; ValueDisplayed: DNP; U/M: EA; Cap_F: 0.0000047; Tolerance_%: 20; ESR_ohm: 0.001; Value1: 0.001 ohm; VDC_V: 6.3; Value2: 6.3V; TaMin_C: -55; TaMax_C: 125; AEC Category: Q200
C142 C147 = GRM155R61E104KA87D: as C29 on sheet PMP12004-HE_sh2
C144 C158 = GRM155R60J102KA01D: CAP, CERM, 1000 pF, 6.3 V, +/- 10%, X5R, 0402; Manufacturer: MuRata; Polarized: N; CompType: Capacitor; Value: 1000pF; U/M: EA; Cap_F: 0.000000001; Tolerance_%: 10; Value1: Unknown; VDC_V: 6.3; Value2: 6.3V; TaMin_C: -55; TaMax_C: 85; AEC Category: Q200
C148-C150 = C1608X5R0J226M080AC: CAP, CERM, 22 µF, 6.3 V, +/- 20%, X5R, 0603; Manufacturer: TDK; Polarized: N; CompType: Capacitor; Value: 22uF; U/M: EA; Cap_F: 0.000022; Tolerance_%: 20; Value1: Unknown; VDC_V: 6.3; Value2: 6.3V; TaMin_C: -55; TaMax_C: 85
J27 J29 = U.FL-R-SMT-1: as J2 on sheet PMP12004-HE_sh2
J28 J30 = 1935776: as J1 on sheet PMP12004-HE_sh1
L6 L7 = 744777001: Inductor, Shielded Drum Core, Metal Composite, 1 µH, 8 A, 0.0084 ohm, SMD; Manufacturer: Wurth Elektronik; Value: 1uH; Ind_H: 1.0E-6; Imax_A: 8; Irms: 8A @ 40C rise; Isat: 9A @ 10% inductance drop; DCR_ohm: 0.0084; Value2: 8A; AEC Category: Q200
R76 R81 = RT0603DRE0710KL: RES, 10.0 k, 0.5%, 0.1 W, 0603; Manufacturer: Yageo America; CompType: Resistor; Value: 10.0k; Res_ohm: 10000; Value_Code: 10k0; Tolerance_%: 0.5; Power_W: 0.1; Value2: 0.1W; VDC_V: 75; TempCo: 50 ppm/C; EIA_Code: E192; U/M: EA; AEC Category: Q200
R77 = RT0603DRE072K49L: RES, 2.49 k, 0.5%, 0.1 W, 0603; Manufacturer: Yageo America; CompType: Resistor; Value: 2.49k; Res_ohm: 2490; Value_Code: 2k49; Tolerance_%: 0.5; Power_W: 0.1; Value2: 0.1W; VDC_V: 75; TempCo: 50 ppm/C; EIA_Code: E192; U/M: EA; AEC Category: Q200
R78 R82 = CRCW040249R9FKED: as R24 on sheet PMP12004-HE_sh2
R79 R84 = RT0603DRE074K99L: RES, 4.99 k, 0.5%, 0.1 W, 0603; Manufacturer: Yageo America; CompType: Resistor; Value: 4.99k; Res_ohm: 4990; Value_Code: 4k99; Tolerance_%: 0.5; Power_W: 0.1; Value2: 0.1W; VDC_V: 75; TempCo: 50 ppm/C; EIA_Code: E192; U/M: EA; AEC Category: Q200
R80 R85 = CRCW04020000Z0ED: as R8 on sheet PMP12004-HE_sh1
R83 = RT0603DRE07619RL: RES, 619, 0.5%, 0.1 W, 0603; Manufacturer: Yageo America; CompType: Resistor; Value: 619; Value_Code: 619R; Tolerance_%: 0.5; Power_W: 0.1; Value2: 0.1W; VDC_V: 75; TempCo: 50 ppm/C; EIA_Code: E192; U/M: EA; AEC Category: Q200
TP49 TP51 = 5000: as TP1 on sheet PMP12004-HE_sh1
TP50 TP52 = 5001: as TP2 on sheet PMP12004-HE_sh1
U3 U4 = TPS74901RGWT: Single Output LDO, 3 A, Adjustable 0.8 to 3.6 V Output, 0.8 to 5.5 V Input, with Programmable Soft Start, 20-pin VQFN (RGW), -40 to 125 degC, Green (RoHS & no Sb/Br); Manufacturer: Texas Instruments; Alternate PartNumber: Equivalent; Accuracy(%): 2; Iout(Max)(A): 3; Power Good: TRUE; Rating: Catalog; SubFamily: Single Channel LDO; Vdo(Typ)(mV): 120; Vin(Max)(V): 5.5; Vin(Min)(V): 0.8; Vout Adj(Max)(V): 3.6

## Sheet PMP12004-HE_sh4.SchDoc: 1.8V & DDR Rails
size 431 x 279 mm; Date: Not shown in title block; ApprovedBy: Not shown in title block; CheckedBy: Not shown in title block; Author: Not shown in title block; CompanyName: Not shown in title block; Engineer: Not shown in title block; Organization: Not shown in title block; Address1: Not shown in title block; Address2: Not shown in title block; Address3: Not shown in title block; Address4: Not shown in title block; DocumentNumber: 4; Revision: Use project parameter SCH_Rev; SheetNumber: 4; SheetTotal: 7; PageSetup: Record=PageOptions¦CenterHorizontal=True¦CenterVertical=True¦PrintScale=1.00¦XCorrection=1.00¦YCorrection=1.00¦PrintKind=0¦BorderSize=5000000¦LeftOffset=0¦BottomOffset=0¦Orientation=2¦PaperLength=1000¦PaperWidth=1000¦Scale=100¦PaperSource=15¦PrintQuality=600¦MediaType=1¦DitherType=10¦PaperKind=Letter¦PrintScaleMode=1
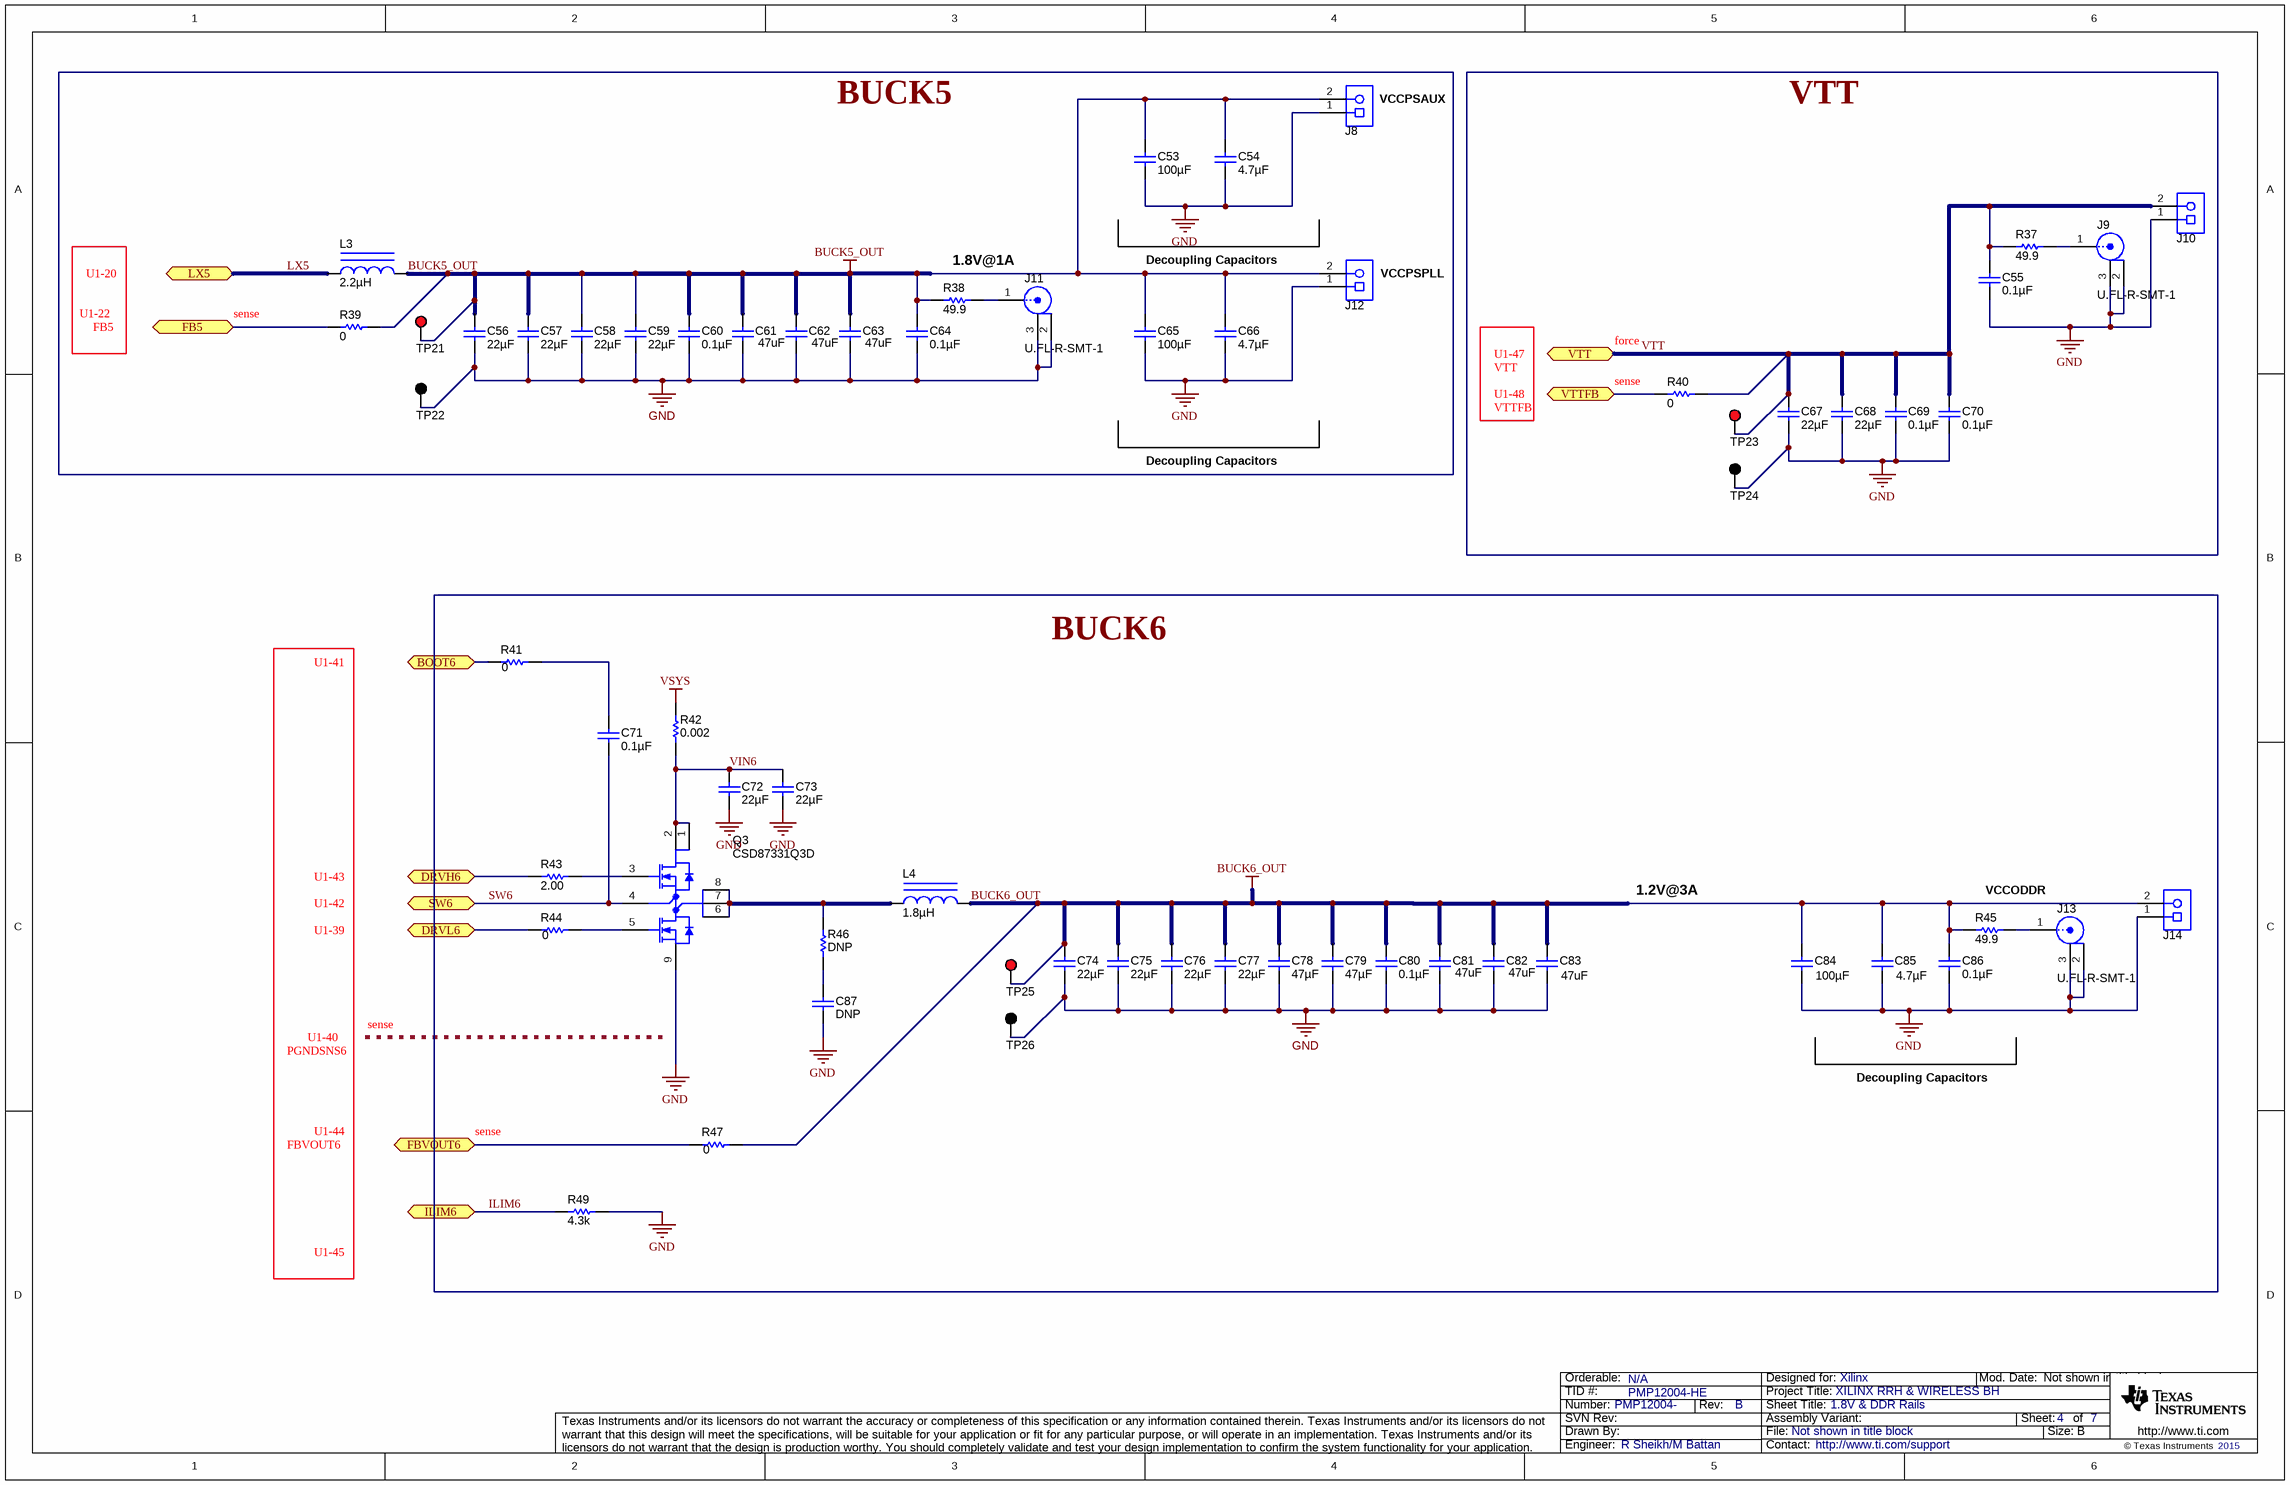
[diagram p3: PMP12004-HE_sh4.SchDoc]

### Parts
C53  ValueDisplayed: 100µF  [0805_HV]  (hidden comment: GRM21BR60G107ME15L)
C54  ValueDisplayed: 4.7µF  [0603]  (hidden comment: GRM188R60J475ME19D)
C55  ValueDisplayed: 0.1µF  [0402]  (hidden comment: GRM155R61E104KA87D)
C56  ValueDisplayed: 22µF  [0603]  (hidden comment: C1608X5R0J226M080AC)
C57  ValueDisplayed: 22µF  [0603]  (hidden comment: C1608X5R0J226M080AC)
C58  ValueDisplayed: 22µF  [0603]  (hidden comment: C1608X5R0J226M080AC)
C59  ValueDisplayed: 22µF  [0603]  (hidden comment: GRM188R60J226MEA0J)
C60  ValueDisplayed: 0.1µF  [0402]  (hidden comment: GRM155R61A104KA01D)
C61  value 47uF  [0805_HV]  (hidden comment: GRM21BR61A476ME15)
C62  value 47uF  [0805_HV]  (hidden comment: GRM21BR61A476ME15)
C63  value 47uF  [0805_HV]  (hidden comment: GRM21BR61A476ME15)
C64  ValueDisplayed: 0.1µF  [0402]  (hidden comment: GRM155R61E104KA87D)
C65  ValueDisplayed: 100µF  [0805_HV]  (hidden comment: GRM21BR60G107ME15L)
C66  ValueDisplayed: 4.7µF  [0603]  (hidden comment: GRM188R60J475ME19D)
C67  ValueDisplayed: 22µF  [0603]  (hidden comment: GRM188R60J226MEA0J)
C68  ValueDisplayed: 22µF  [0603]  (hidden comment: GRM188R60J226MEA0J)
C69  ValueDisplayed: 0.1µF  [0402]  (hidden comment: GRM155R61A104KA01D)
C70  ValueDisplayed: 0.1µF  [0402]  (hidden comment: GRM155R61A104KA01D)
C71  ValueDisplayed: 0.1µF  [0402]  (hidden comment: GRM155R61A104KA01D)
C72  ValueDisplayed: 22µF  [0805_HV]  (hidden comment: GRM21BR61E226ME44)
C73  ValueDisplayed: 22µF  [0805_HV]  (hidden comment: GRM21BR61E226ME44)
C74  ValueDisplayed: 22µF  [0603]  (hidden comment: GRM188R60J226MEA0J)
C75  ValueDisplayed: 22µF  [0603]  (hidden comment: GRM188R60J226MEA0J)
C76  ValueDisplayed: 22µF  [0603]  (hidden comment: GRM188R60J226MEA0J)
C77  ValueDisplayed: 22µF  [0603]  (hidden comment: GRM188R60J226MEA0J)
C78  ValueDisplayed: 47µF  [0603_120]  (hidden comment: ZRB18AR60G476ME01)
C79  ValueDisplayed: 47µF  [0603_120]  (hidden comment: ZRB18AR60G476ME01)
C80  ValueDisplayed: 0.1µF  [0402]  (hidden comment: GRM155R61A104KA01D)
C81  value 47uF  [0805_HV]  (hidden comment: GRM21BR61A476ME15)
C82  value 47uF  [0805_HV]  (hidden comment: GRM21BR61A476ME15)
C83  value 47uF  [0805_HV]  (hidden comment: GRM21BR61A476ME15)
C84  value 100µF  [0805_HV]  (hidden comment: GRM21BR60G107ME15L)
C85  value 4.7µF  [0603]  (hidden comment: GRM188R60J475ME19D)
C86  ValueDisplayed: 0.1µF  [0402]  (hidden comment: GRM155R61E104KA87D)
C87  ValueDisplayed: DNP  [0402]  (hidden comment: GRM155R71E682KA01D)
J8  1935776  [Phoenix_1935776]  (value not drawn)
J9  U.FL-R-SMT-1  [CONN_UFL-R-SMT-1]
J10  1935776  [Phoenix_1935776]  (value not drawn)
J11  U.FL-R-SMT-1  [CONN_UFL-R-SMT-1]
J12  1935776  [Phoenix_1935776]  (value not drawn)
J13  U.FL-R-SMT-1  [CONN_UFL-R-SMT-1]
J14  1935776  [Phoenix_1935776]  (value not drawn)
L3  ValueDisplayed: 2.2µH  [WE-LHMI_1040]  (hidden comment: 74437368022)
L4  ValueDisplayed: 1.8µH  [WE-HC6]  (hidden comment: 744325180)
Q3  CSD87331Q3D  [TRANS_NexFET_Q3D]
R37  ValueDisplayed: 49.9  [0402]  (hidden comment: CRCW040249R9FKED)
R38  ValueDisplayed: 49.9  [0402]  (hidden comment: CRCW040249R9FKED)
R39  ValueDisplayed: 0  [0402]  (hidden comment: CRCW04020000Z0ED)
R40  ValueDisplayed: 0  [0402]  (hidden comment: CRCW04020000Z0ED)
R41  ValueDisplayed: 0  [0402]  (hidden comment: CRCW04020000Z0ED)
R42  ValueDisplayed: 0.002  [0508]  (hidden comment: KRL2012E-M-R002-G-T5)
R43  ValueDisplayed: 2.00  [0402]  (hidden comment: CRCW04022R00FKED)
R44  ValueDisplayed: 0  [0402]  (hidden comment: CRCW04020000Z0ED)
R45  ValueDisplayed: 49.9  [0402]  (hidden comment: CRCW040249R9FKED)
R46  ValueDisplayed: DNP  [0402]  (hidden comment: CRCW04022R20JNED)
R47  ValueDisplayed: 0  [0402]  (hidden comment: CRCW04020000Z0ED)
R49  ValueDisplayed: 4.3k  [0402]  (hidden comment: CRCW04024K30JNED)
TP21  5000  [Keystone5000]  (value not drawn)
TP22  5001  [Keystone5001]  (value not drawn)
TP23  5000  [Keystone5000]  (value not drawn)
TP24  5001  [Keystone5001]  (value not drawn)
TP25  5000  [Keystone5000]  (value not drawn)
TP26  5001  [Keystone5001]  (value not drawn)

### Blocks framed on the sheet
BUCK5: C53 C54 C56-C66 J8 J11 J12 L3 R38 R39 TP21 TP22
VTT: C55 C67-C70 J9 J10 R37 R40 TP23 TP24
BUCK6: C71-C87 J13 J14 L4 Q3 R41-R47 R49 TP25 TP26

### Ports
BOOT6 (bidir), DRVH6 (bidir), DRVL6 (bidir), FB5 (bidir), FBVOUT6 (bidir), ILIM6 (bidir), LX5 (bidir), SW6 (bidir), VTT (bidir), VTTFB (bidir)

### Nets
BUCK5_OUT: C53.1 C54.1 C56.1 C57.1 C58.1 C59.1 C60.1 C61.1 C62.1 C63.1 C64.1 C65.1 C66.1 J8.2 J12.2 L3.2 R38.1 R39.2 TP21.1
BUCK6_OUT: C74.1 C75.1 C76.1 C77.1 C78.1 C79.1 C80.1 C81.1 C82.1 C83.1 C84.1 C85.1 C86.1 J14.2 L4.2 R45.1 R47.2 TP25.1
GND: C53.2 C54.2 C55.2 C56.2 C57.2 C58.2 C59.2 C60.2 C61.2 C62.2 C63.2 C64.2 C65.2 C66.2 C67.2 C68.2 C69.2 C70.2 C72.2 C73.2 C74.2 C75.2 C76.2 C77.2 C78.2 C79.2 C80.2 C81.2 C82.2 C83.2 C84.2 C85.2 C86.2 C87.2 J8.1 J9.2 J9.3 J10.1 J11.2 J11.3 J12.1 J13.2 J13.3 J14.1 Q3.9(PGND) R49.2 TP22.1 TP24.1 TP26.1
VSYS: R42.1
BOOT6: R41.1 ; port BOOT6
DRVH6: R43.1 ; port DRVH6
DRVL6: R44.1 ; port DRVL6
FB5: R39.1 ; port FB5
FBVOUT6: R47.1 ; port FBVOUT6
ILIM6: R49.1 ; port ILIM6
LX5: L3.1 ; port LX5
SW6: C71.1 Q3.4(TGR) ; port SW6
VIN6: C72.1 C73.1 Q3.1(VIN) Q3.2(VIN) R42.2
VTT: C55.1 C67.1 C68.1 C69.1 C70.1 J10.2 R37.1 R40.2 TP23.1 ; port VTT
VTTFB: R40.1 ; port VTTFB
NetC71_2: C71.2 R41.2
NetC87_1: C87.1 R46.1
NetJ9_1: J9.1 R37.2
NetJ11_1: J11.1 R38.2
NetJ13_1: J13.1 R45.2
NetL4_1: L4.1 Q3.6(VSW) Q3.7(VSW) Q3.8(VSW) R46.2
NetQ3_3: Q3.3(TG) R43.2
NetQ3_5: Q3.5(BG) R44.2

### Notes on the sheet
- (near J8) VCCPSAUX
- U1-20
- 1.8V@1A
- Decoupling Capacitors
- (near J12) VCCPSPLL
- U1-22
- FB5
- sense
- U1-47
- VTT
- (near R40) force
- U1-48
- VTTFB
- (near R40) sense
- U1-41
- U1-43
- U1-42
- 1.2V@3A
- VCCODDR
- U1-39
- U1-40
- PGNDSNS6
- FBVOUT6
- U1-44
- U1-45

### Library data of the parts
C53 C65 = GRM21BR60G107ME15L: as C34 on sheet PMP12004-HE_sh2
C54 C66 = GRM188R60J475ME19D: as C35 on sheet PMP12004-HE_sh2
C55 C64 C86 = GRM155R61E104KA87D: as C29 on sheet PMP12004-HE_sh2
C56-C58 = C1608X5R0J226M080AC: as C148 on sheet PMP12004-HE_sh3
C59 C67 C68 C74-C77 = GRM188R60J226MEA0J: as C19 on sheet PMP12004-HE_sh2
C60 C69-C71 C80 = GRM155R61A104KA01D: as C12 on sheet PMP12004-HE_sh1
C61-C63 C81-C83 = GRM21BR61A476ME15: as C26 on sheet PMP12004-HE_sh2
C72 C73 = GRM21BR61E226ME44: as C16 on sheet PMP12004-HE_sh2
C78 C79 = ZRB18AR60G476ME01: CAP, CERM, 47 µF, 4 V, +/- 20%, X5R, 0603; Manufacturer: MuRata; Polarized: N; CompType: Capacitor; Value: 47uF; U/M: EA; Cap_F: 0.000047; Tolerance_%: 20; Value1: Unknown; VDC_V: 4; Value2: 4V; TaMin_C: -55; TaMax_C: 85; Cap_Case: 0603; AEC Category: Q200
C84 = GRM21BR60G107ME15L: as C140 on sheet PMP12004-HE_sh3
C85 = GRM188R60J475ME19D: as C141 on sheet PMP12004-HE_sh3
C87 = GRM155R71E682KA01D: as C30 on sheet PMP12004-HE_sh2
J8 J10 J12 J14 = 1935776: as J1 on sheet PMP12004-HE_sh1
J9 J11 J13 = U.FL-R-SMT-1: as J2 on sheet PMP12004-HE_sh2
L3 = 74437368022: as L1 on sheet PMP12004-HE_sh2
L4 = 744325180: as L2 on sheet PMP12004-HE_sh2
Q3 = CSD87331Q3D: as Q1 on sheet PMP12004-HE_sh2
R37 R38 R45 = CRCW040249R9FKED: as R24 on sheet PMP12004-HE_sh2
R39-R41 R44 R47 = CRCW04020000Z0ED: as R8 on sheet PMP12004-HE_sh1
R42 = KRL2012E-M-R002-G-T5: as R1 on sheet PMP12004-HE_sh1
R43 = CRCW04022R00FKED: as R22 on sheet PMP12004-HE_sh2
R46 = CRCW04022R20JNED: as R25 on sheet PMP12004-HE_sh2
R49 = CRCW04024K30JNED: RES, 4.3 k, 5%, 0.063 W, 0402; Manufacturer: Vishay-Dale; CompType: Resistor; Value: 4.3k; Res_ohm: 4300; Value_Code: 4k30; Tolerance_%: 5; Power_W: 0.063; Value2: 0.063W; VDC_V: 50; TempCo: 200 ppm/C; EIA_Code: E24; U/M: EA; AEC Category: Q200
TP21 TP23 TP25 = 5000: as TP1 on sheet PMP12004-HE_sh1
TP22 TP24 TP26 = 5001: as TP2 on sheet PMP12004-HE_sh1

## Sheet PMP12004-HE_sh5.SchDoc: GPOs, I2C, LDOs & SWs
size 431 x 279 mm; Date: Not shown in title block; ApprovedBy: Not shown in title block; CheckedBy: Not shown in title block; Author: Not shown in title block; CompanyName: Not shown in title block; Engineer: Not shown in title block; Organization: Not shown in title block; Address1: Not shown in title block; Address2: Not shown in title block; Address3: Not shown in title block; Address4: Not shown in title block; DocumentNumber: 5; Revision: Use project parameter SCH_Rev; SheetNumber: 5; SheetTotal: 7; PageSetup: Record=PageOptions¦CenterHorizontal=True¦CenterVertical=True¦PrintScale=1.00¦XCorrection=1.00¦YCorrection=1.00¦PrintKind=0¦BorderSize=5000000¦LeftOffset=0¦BottomOffset=0¦Orientation=2¦PaperLength=1000¦PaperWidth=1000¦Scale=100¦PaperSource=15¦PrintQuality=600¦MediaType=1¦DitherType=10¦PaperKind=Letter¦PrintScaleMode=1
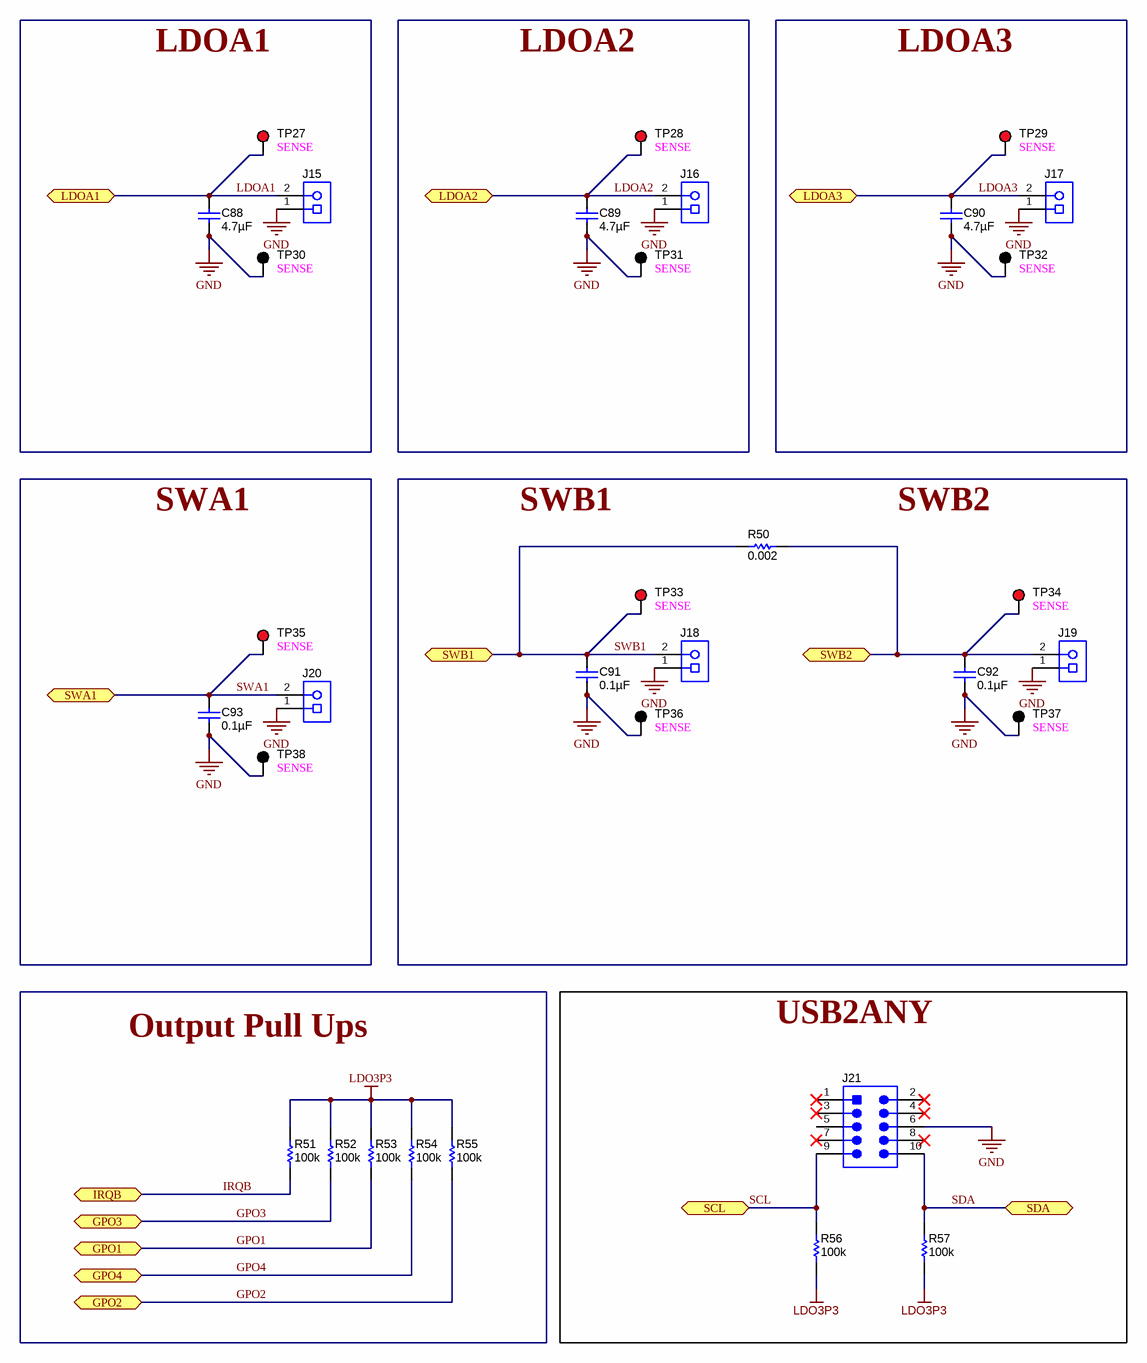
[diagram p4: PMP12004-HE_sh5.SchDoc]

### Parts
C88  ValueDisplayed: 4.7µF  [0402]  (hidden comment: GRM155R60J475ME47D)
C89  ValueDisplayed: 4.7µF  [0402]  (hidden comment: GRM155R60J475ME47D)
C90  ValueDisplayed: 4.7µF  [0402]  (hidden comment: GRM155R60J475ME47D)
C91  ValueDisplayed: 0.1µF  [0402]  (hidden comment: GRM155R61A104KA01D)
C92  ValueDisplayed: 0.1µF  [0402]  (hidden comment: GRM155R61A104KA01D)
C93  ValueDisplayed: 0.1µF  [0402]  (hidden comment: GRM155R61A104KA01D)
J15  1935776  [Phoenix_1935776]  (value not drawn)
J16  1935776  [Phoenix_1935776]  (value not drawn)
J17  1935776  [Phoenix_1935776]  (value not drawn)
J18  1935776  [Phoenix_1935776]  (value not drawn)
J19  1935776  [Phoenix_1935776]  (value not drawn)
J20  1935776  [Phoenix_1935776]  (value not drawn)
J21  N2510-6002-RB  [CONN_2510-6002]  (value not drawn)
R50  ValueDisplayed: 0.002  [0508]  (hidden comment: KRL2012E-M-R002-G-T5)
R51  ValueDisplayed: 100k  [0402]  (hidden comment: CRCW0402100KFKED)
R52  ValueDisplayed: 100k  [0402]  (hidden comment: CRCW0402100KFKED)
R53  ValueDisplayed: 100k  [0402]  (hidden comment: CRCW0402100KFKED)
R54  ValueDisplayed: 100k  [0402]  (hidden comment: CRCW0402100KFKED)
R55  ValueDisplayed: 100k  [0402]  (hidden comment: CRCW0402100KFKED)
R56  ValueDisplayed: 100k  [0402]  (hidden comment: CRCW0402100KFKED)
R57  ValueDisplayed: 100k  [0402]  (hidden comment: CRCW0402100KFKED)
TP27  5000  [Keystone5000]  (value not drawn)
TP28  5000  [Keystone5000]  (value not drawn)
TP29  5000  [Keystone5000]  (value not drawn)
TP30  5001  [Keystone5001]  (value not drawn)
TP31  5001  [Keystone5001]  (value not drawn)
TP32  5001  [Keystone5001]  (value not drawn)
TP33  5000  [Keystone5000]  (value not drawn)
TP34  5000  [Keystone5000]  (value not drawn)
TP35  5000  [Keystone5000]  (value not drawn)
TP36  5001  [Keystone5001]  (value not drawn)
TP37  5001  [Keystone5001]  (value not drawn)
TP38  5001  [Keystone5001]  (value not drawn)

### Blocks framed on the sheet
LDOA1: C88 J15 TP27 TP30
LDOA2: C89 J16 TP28 TP31
LDOA3: C90 J17 TP29 TP32
SWA1: C93 J20 TP35 TP38
Output Pull Ups: R51-R55
USB2ANY: J21 R56 R57

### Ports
GPO1 (bidir), GPO2 (bidir), GPO3 (bidir), GPO4 (bidir), IRQB (bidir), LDOA1 (bidir), LDOA2 (bidir), LDOA3 (bidir), SCL (bidir), SDA (bidir), SWA1 (bidir), SWB1 (bidir), SWB2 (bidir)

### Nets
GND: C88.2 C89.2 C90.2 C91.2 C92.2 C93.2 J15.1 J16.1 J17.1 J18.1 J19.1 J20.1 J21.6 TP30.1 TP31.1 TP32.1 TP36.1 TP37.1 TP38.1
LDO3P3: R51.2 R52.2 R53.2 R54.2 R55.2 R56.1 R57.1
GPO1: R53.1 ; port GPO1
GPO2: R55.1 ; port GPO2
GPO3: R52.1 ; port GPO3
GPO4: R54.1 ; port GPO4
IRQB: R51.1 ; port IRQB
LDOA1: C88.1 J15.2 TP27.1 ; port LDOA1
LDOA2: C89.1 J16.2 TP28.1 ; port LDOA2
LDOA3: C90.1 J17.2 TP29.1 ; port LDOA3
SCL: J21.9 R56.2 ; port SCL
SDA: J21.10 R57.2 ; port SDA
SWA1: C93.1 J20.2 TP35.1 ; port SWA1
SWB1: C91.1 J18.2 R50.2 TP33.1 ; port SWB1
SWB2: C92.1 J19.2 R50.1 TP34.1 ; port SWB2

Not connected (* = marked no-connect by the designer): J21 1* 2* 3* 4* 5 7* 8*

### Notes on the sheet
- (near TP27) SENSE
- (near TP28) SENSE
- (near TP29) SENSE
- (near TP30) SENSE
- (near TP31) SENSE
- (near TP32) SENSE
- SWB1
- SWB2
- (near TP33) SENSE
- (near TP34) SENSE
- (near TP35) SENSE
- (near TP36) SENSE
- (near TP37) SENSE
- (near TP38) SENSE

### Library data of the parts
C88-C90 = GRM155R60J475ME47D: as C8 on sheet PMP12004-HE_sh1
C91-C93 = GRM155R61A104KA01D: as C12 on sheet PMP12004-HE_sh1
J15-J20 = 1935776: as J1 on sheet PMP12004-HE_sh1
J21 = N2510-6002-RB: Header (shrouded), 100mil, 5x2, High-Temperature, Gold, TH; Manufacturer: 3M; SymbolCreator: a0412235; U/M: EA
R50 = KRL2012E-M-R002-G-T5: as R1 on sheet PMP12004-HE_sh1
R51-R55 = CRCW0402100KFKED: RES, 100 k, 1%, 0.063 W, 0402; Manufacturer: Vishay-Dale; CompType: Resistor; Value: 100k; Res_ohm: 100000; Tolerance_%: 1; Power_W: 0.063; Value2: 0.063W; VDC_V: 50; TempCo: 100 ppm/C; EIA_Code: E96; U/M: EA
R56 R57 = CRCW0402100KFKED: RES, 100 k, 1%, 0.063 W, 0402; Manufacturer: Vishay-Dale; CompType: Resistor; Value: 100k; Res_ohm: 100000; Tolerance_%: 1; Power_W: 0.063; Value2: 0.063W; VDC_V: 50; TempCo: 100 ppm/C; EIA_Code: E96; U/M: EA; AEC Category: Q200
TP27-TP29 TP33-TP35 = 5000: as TP1 on sheet PMP12004-HE_sh1
TP30-TP32 TP36-TP38 = 5001: as TP2 on sheet PMP12004-HE_sh1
